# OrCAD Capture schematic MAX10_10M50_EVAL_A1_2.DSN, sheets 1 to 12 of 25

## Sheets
1 Title, Note, Block Diagram: title: MAX 10 FPGA 10M50 Evaluation Kit (6XX-44364R); rev: A1.2; company: Altera Technical Service, No.888 Bi Bo Road, Shanghai
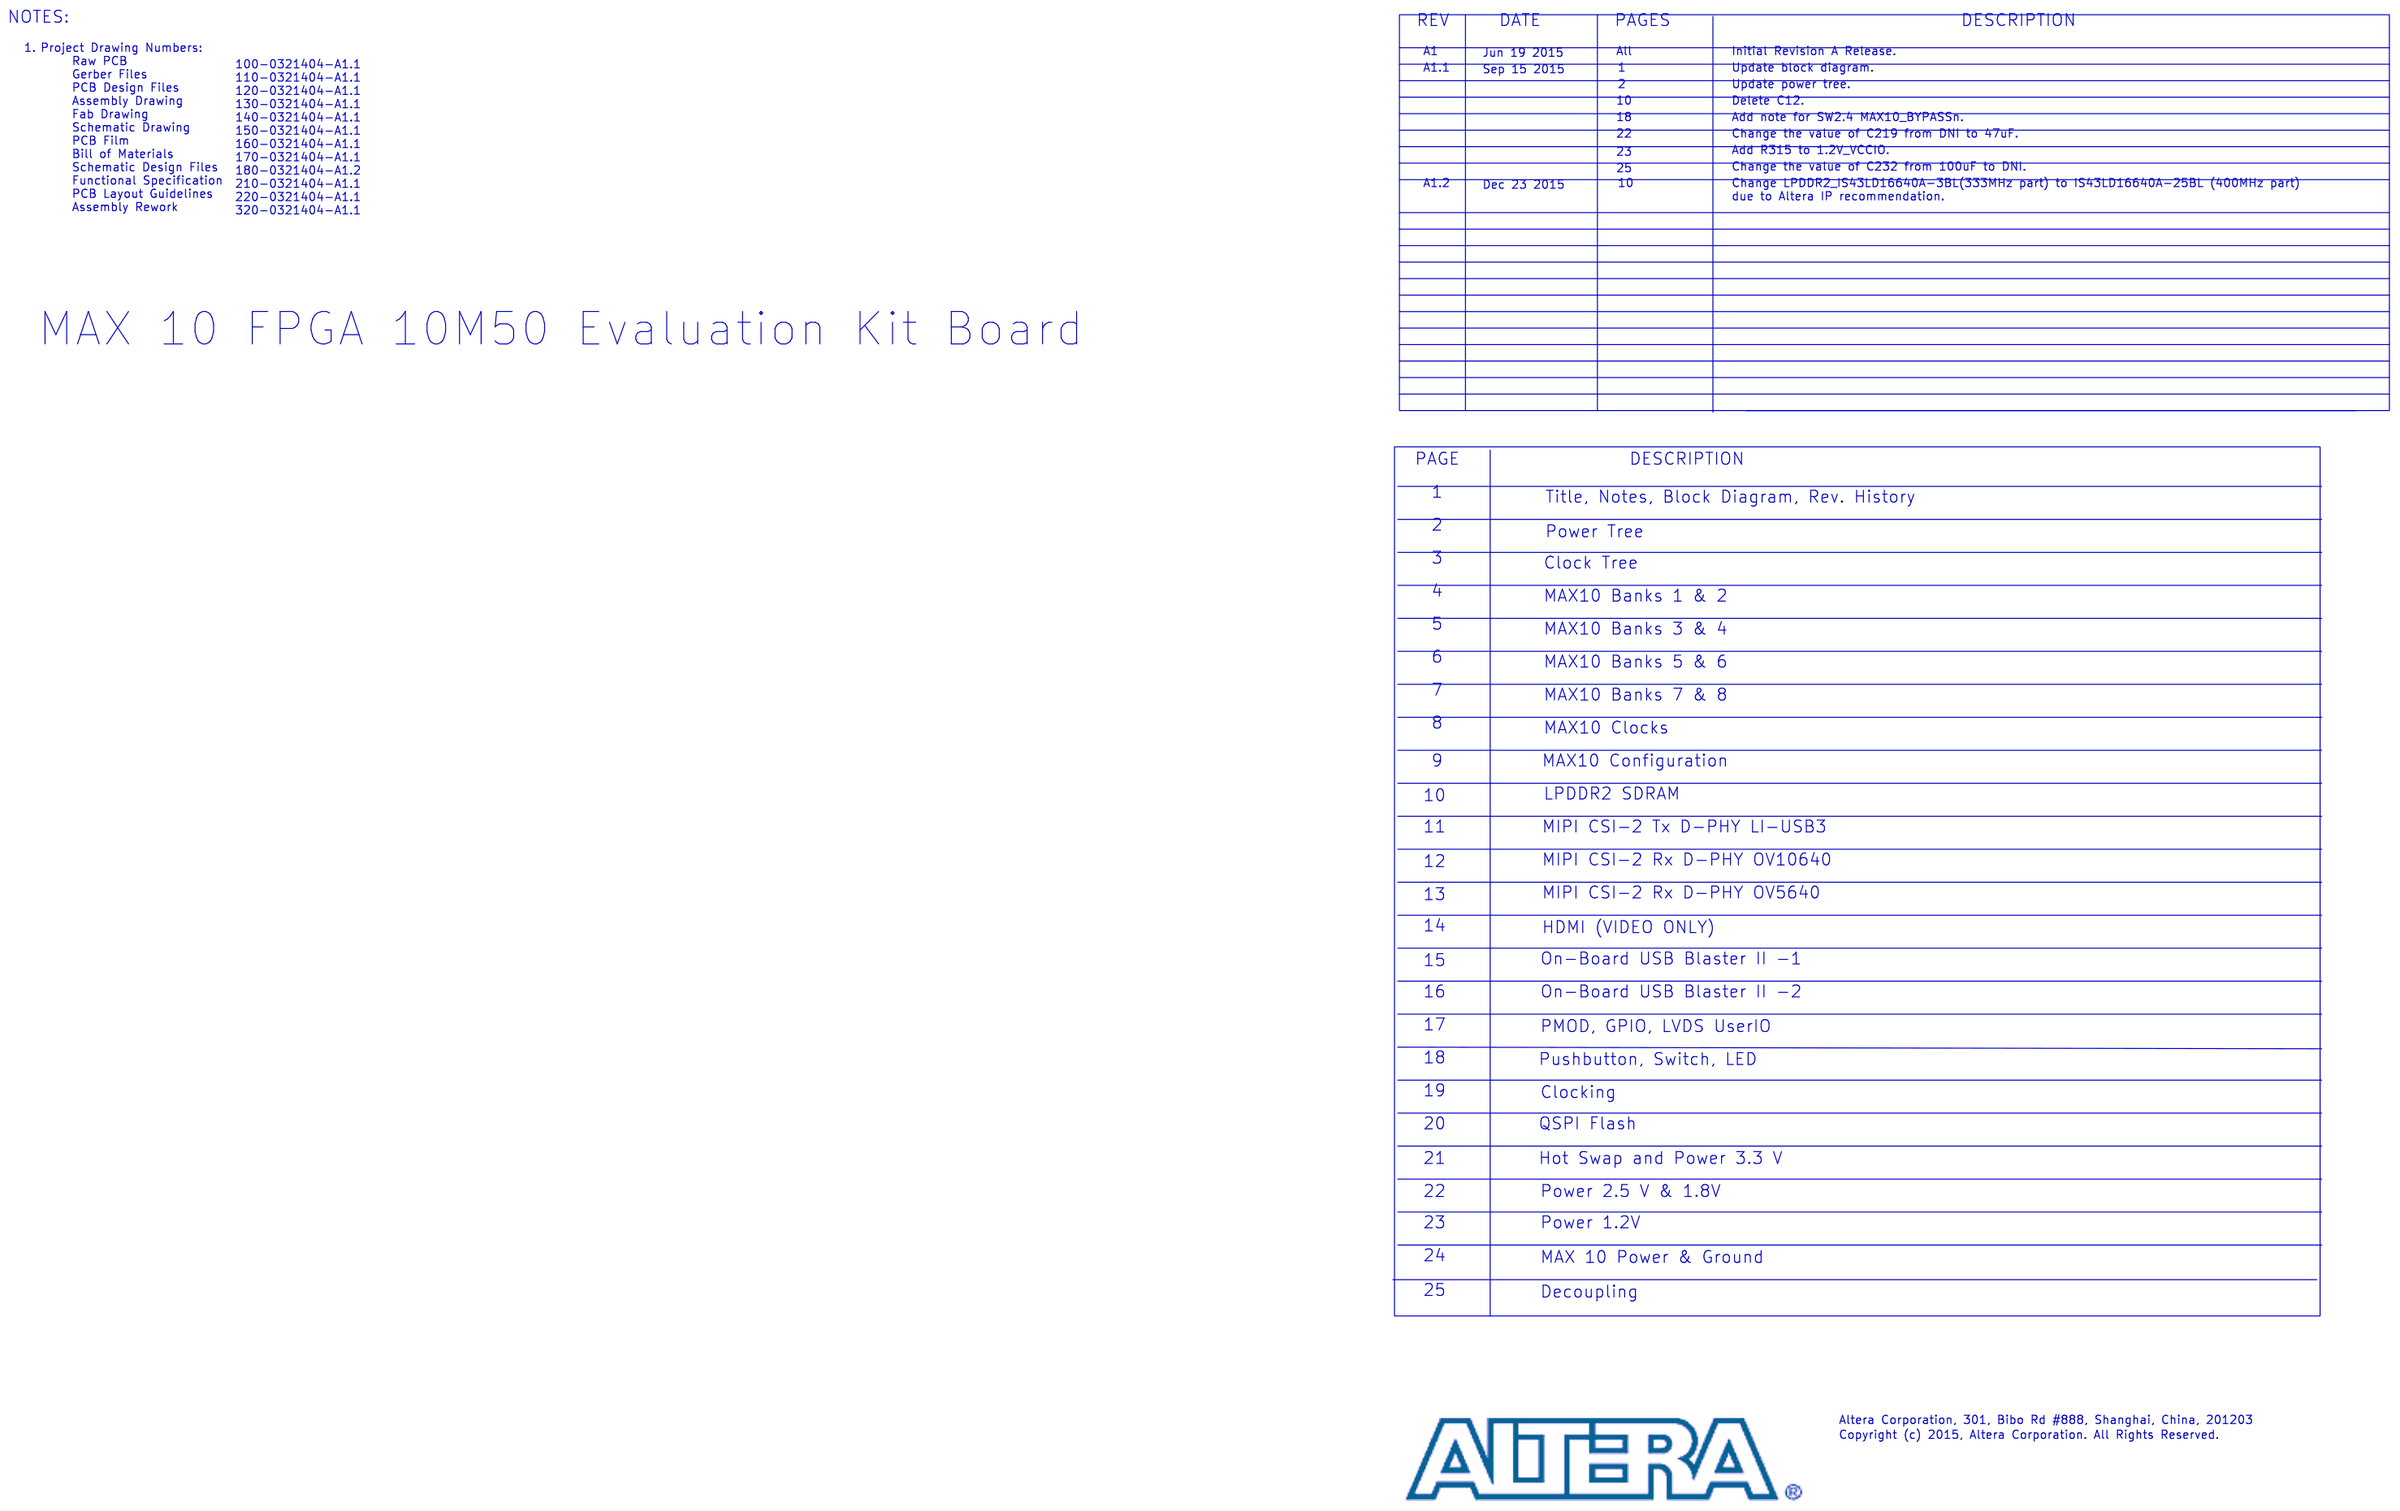
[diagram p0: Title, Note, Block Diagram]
2 Power Tree
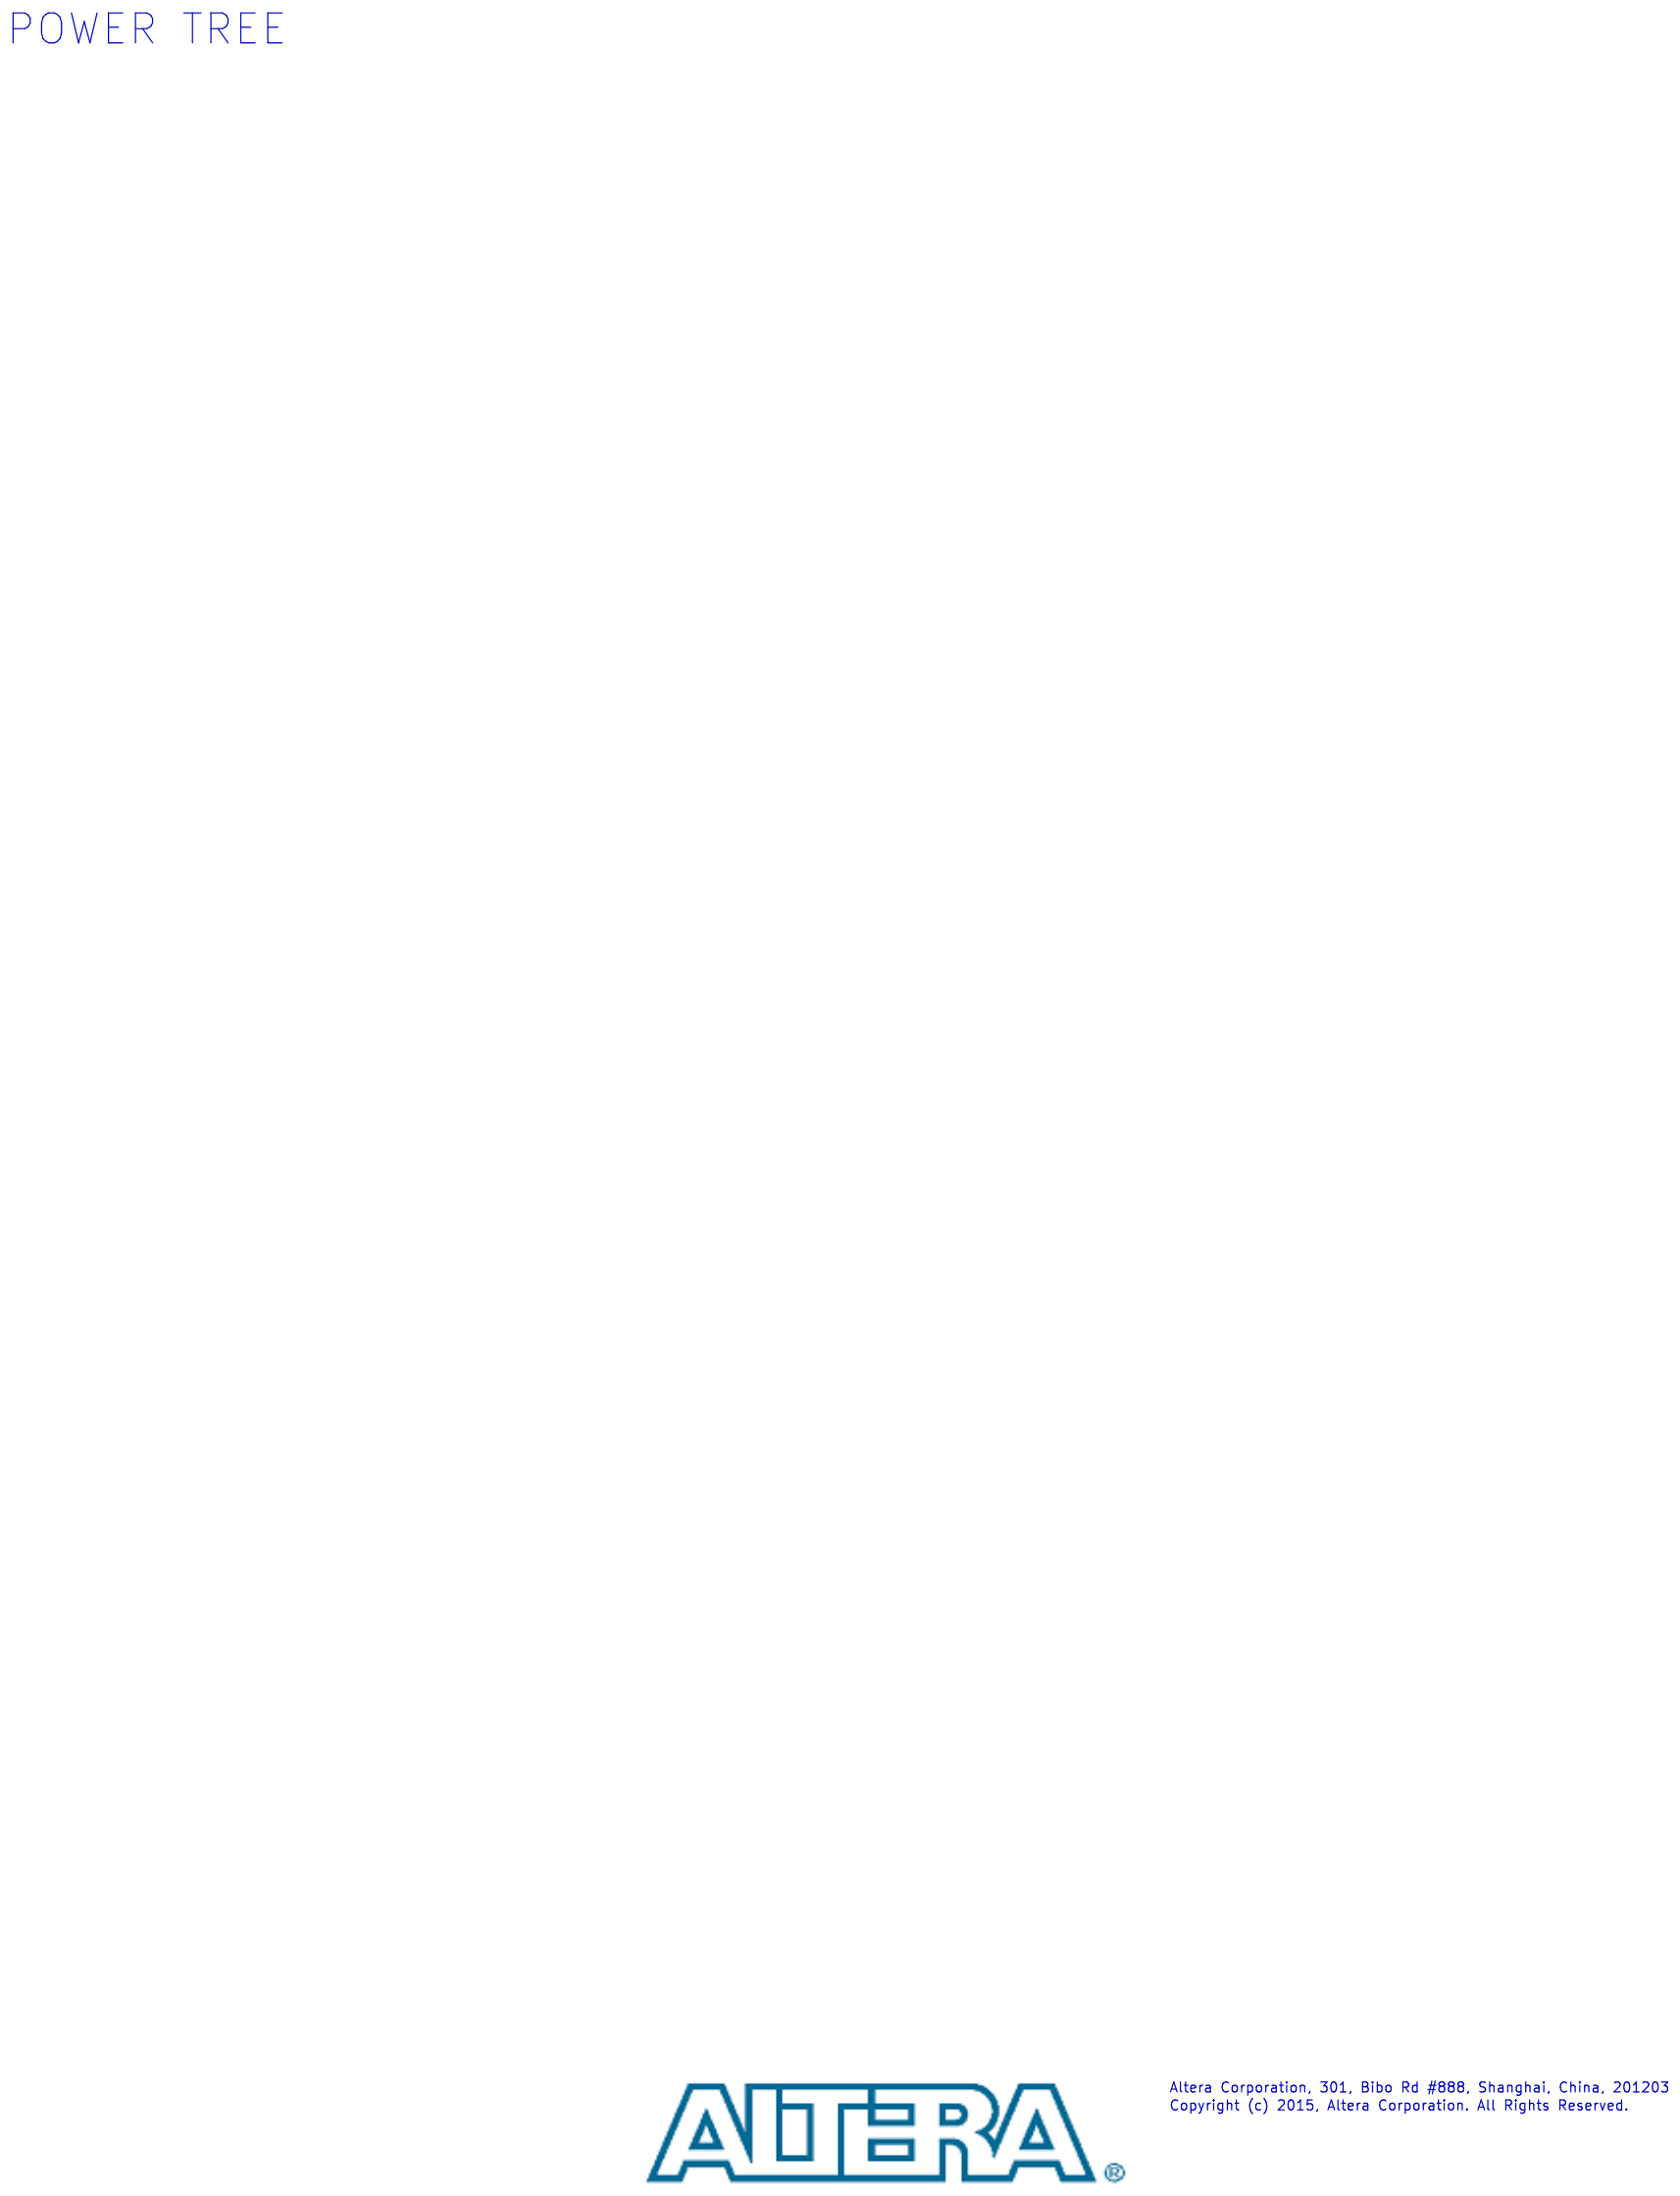
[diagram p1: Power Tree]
3 Clock Tree
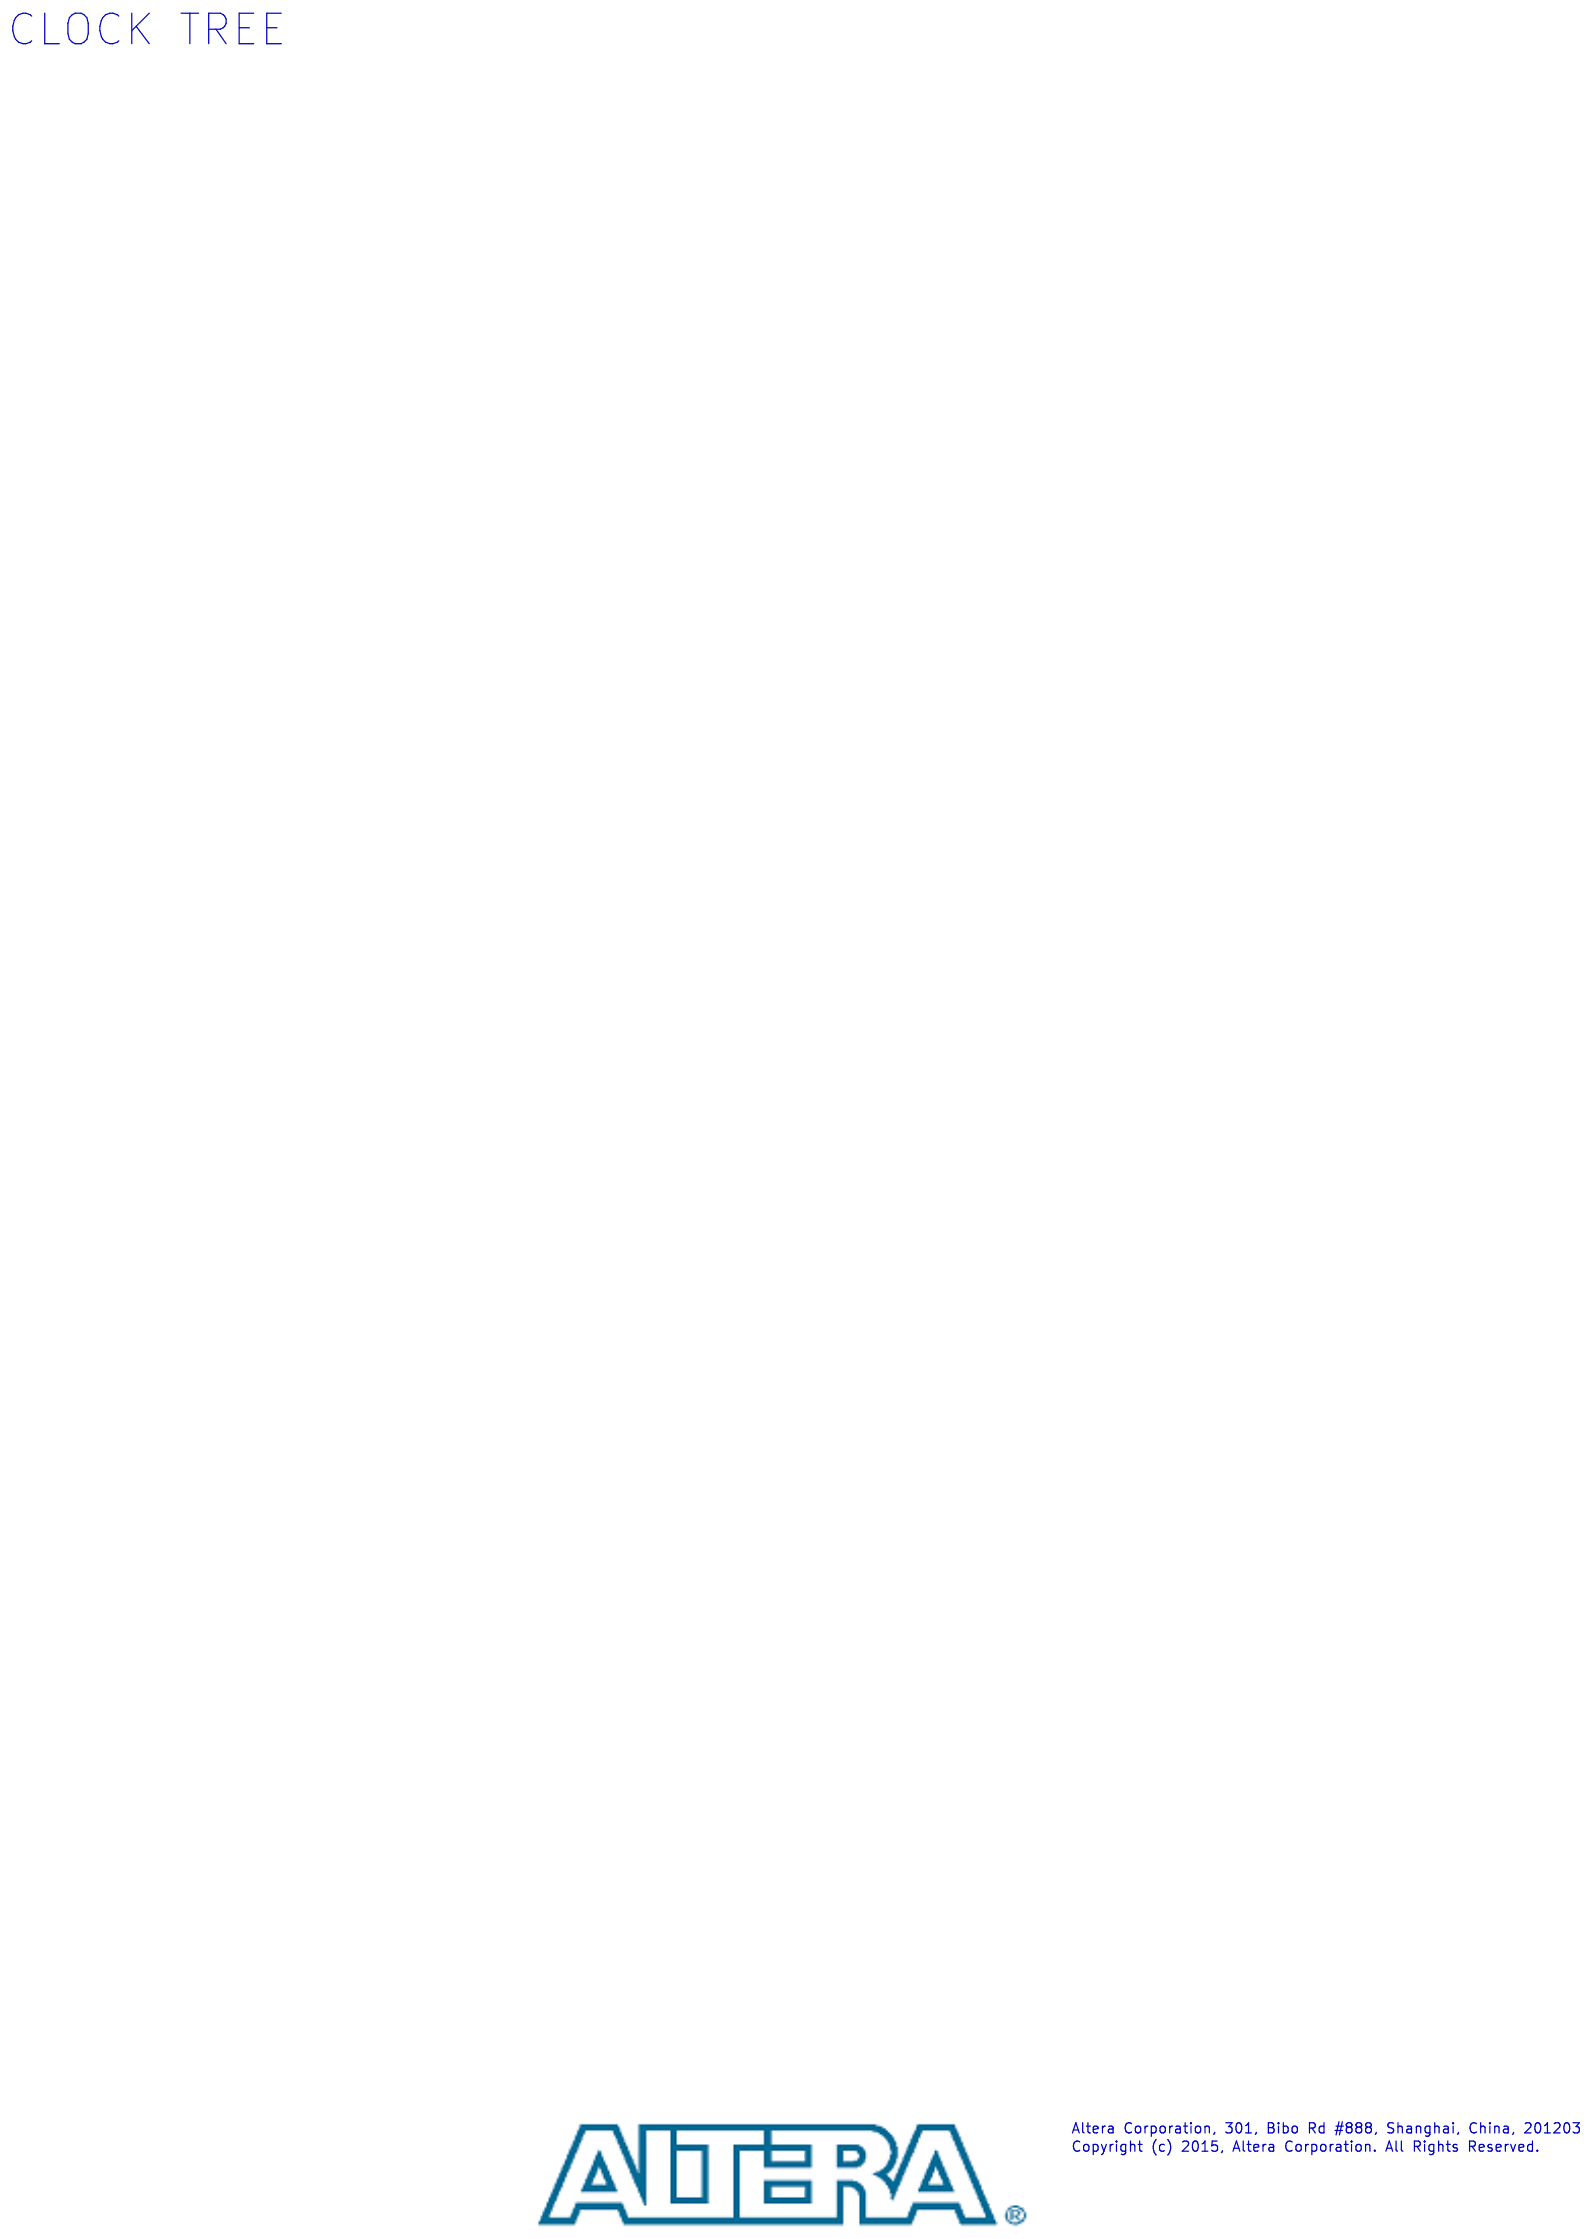
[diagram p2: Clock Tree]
4 MAX 10 Banks 1 & 2: size A3
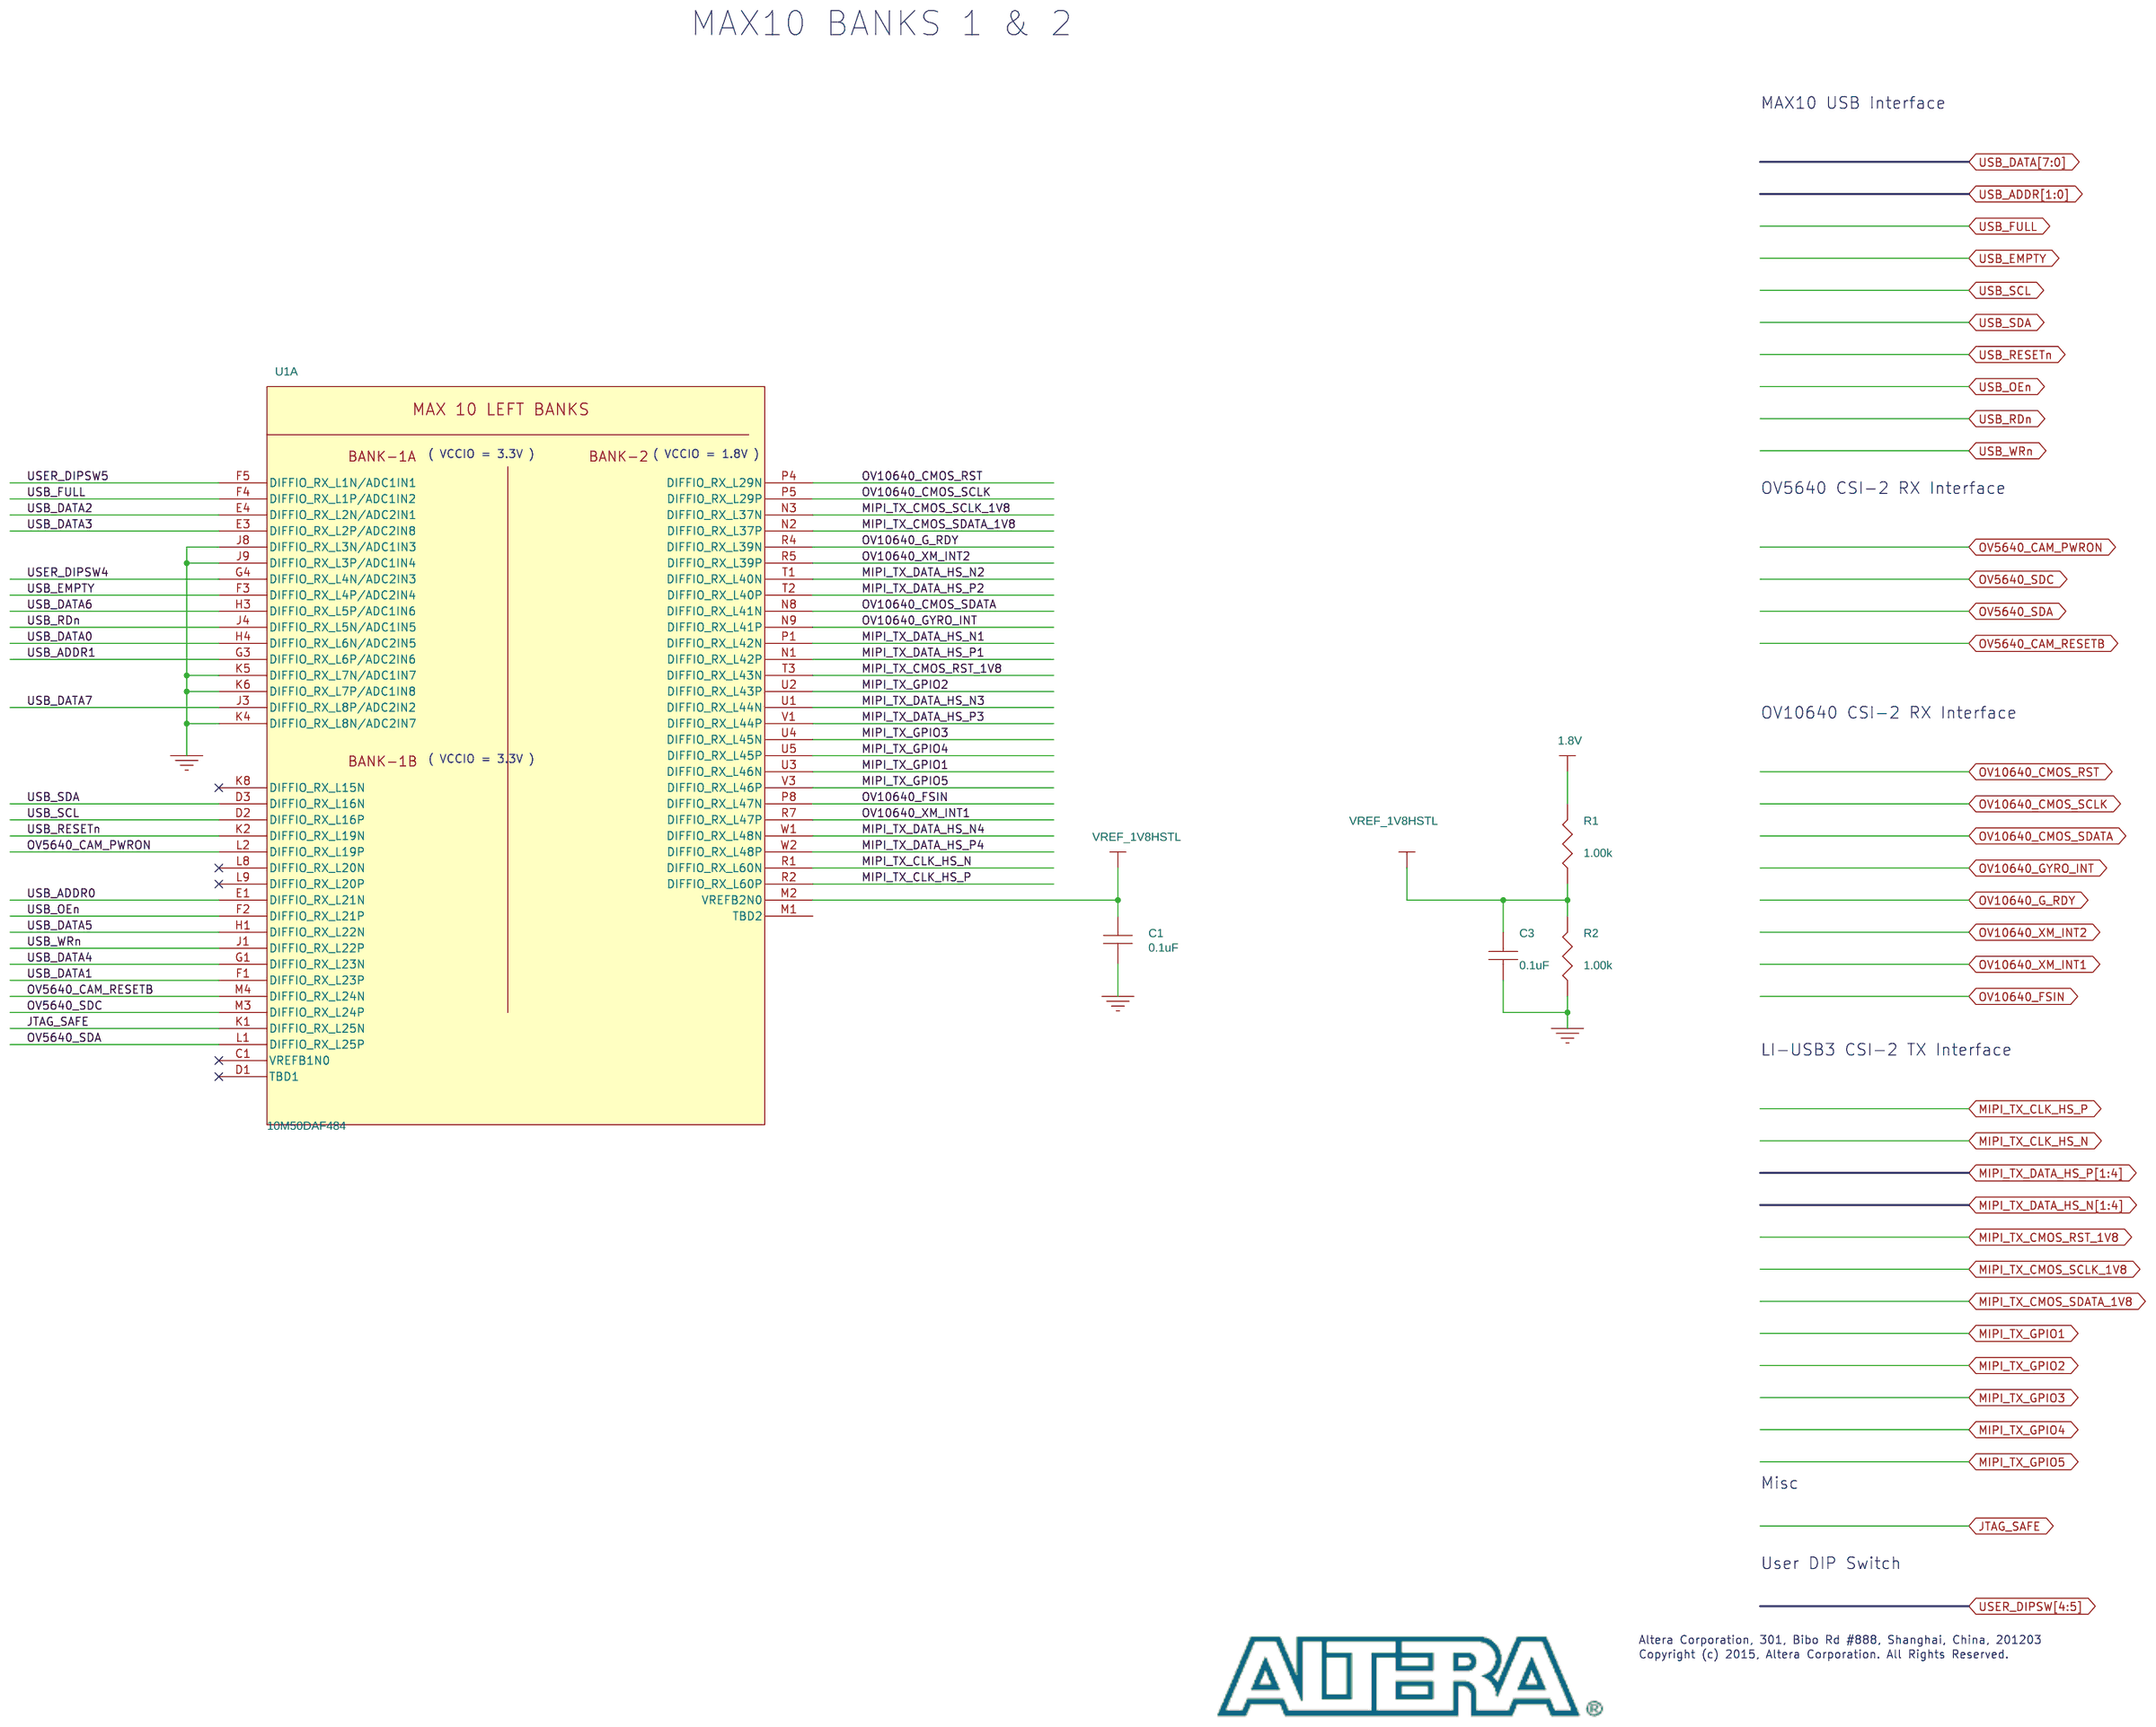
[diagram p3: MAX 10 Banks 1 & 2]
5 MAX 10 Banks 3 & 4: size A3
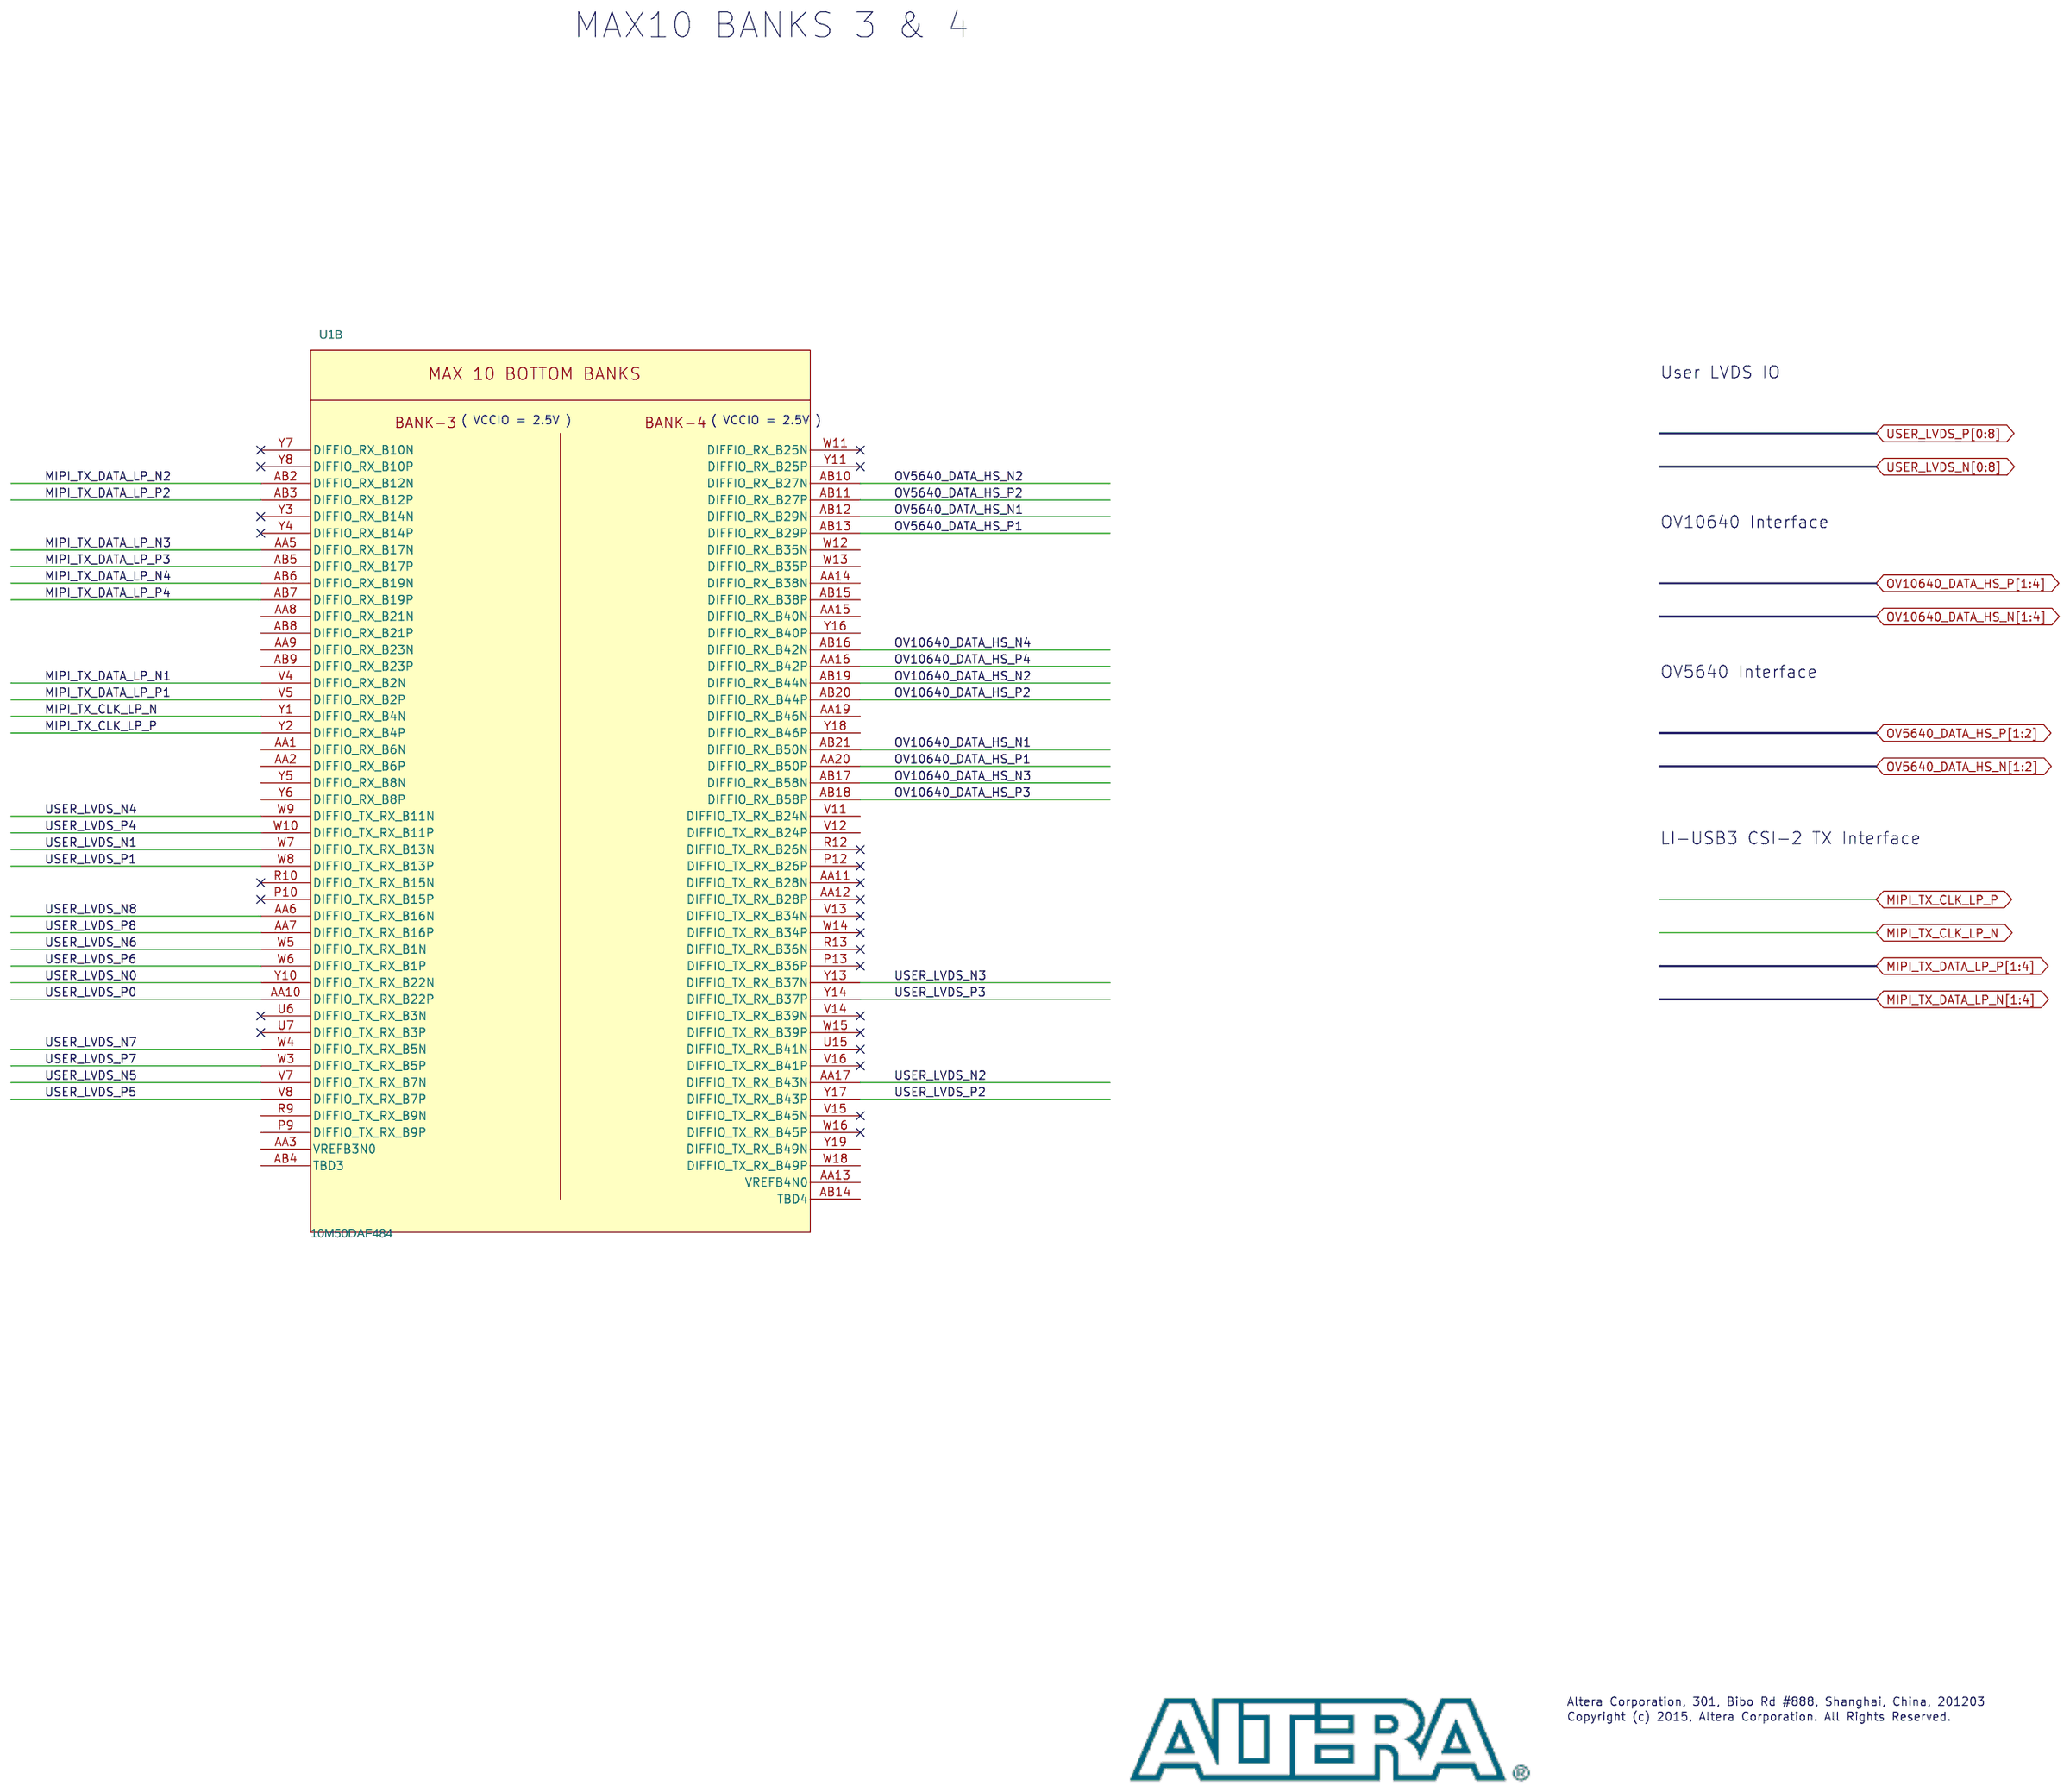
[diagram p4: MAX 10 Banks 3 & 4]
6 MAX 10 Banks 5 & 6: size A3
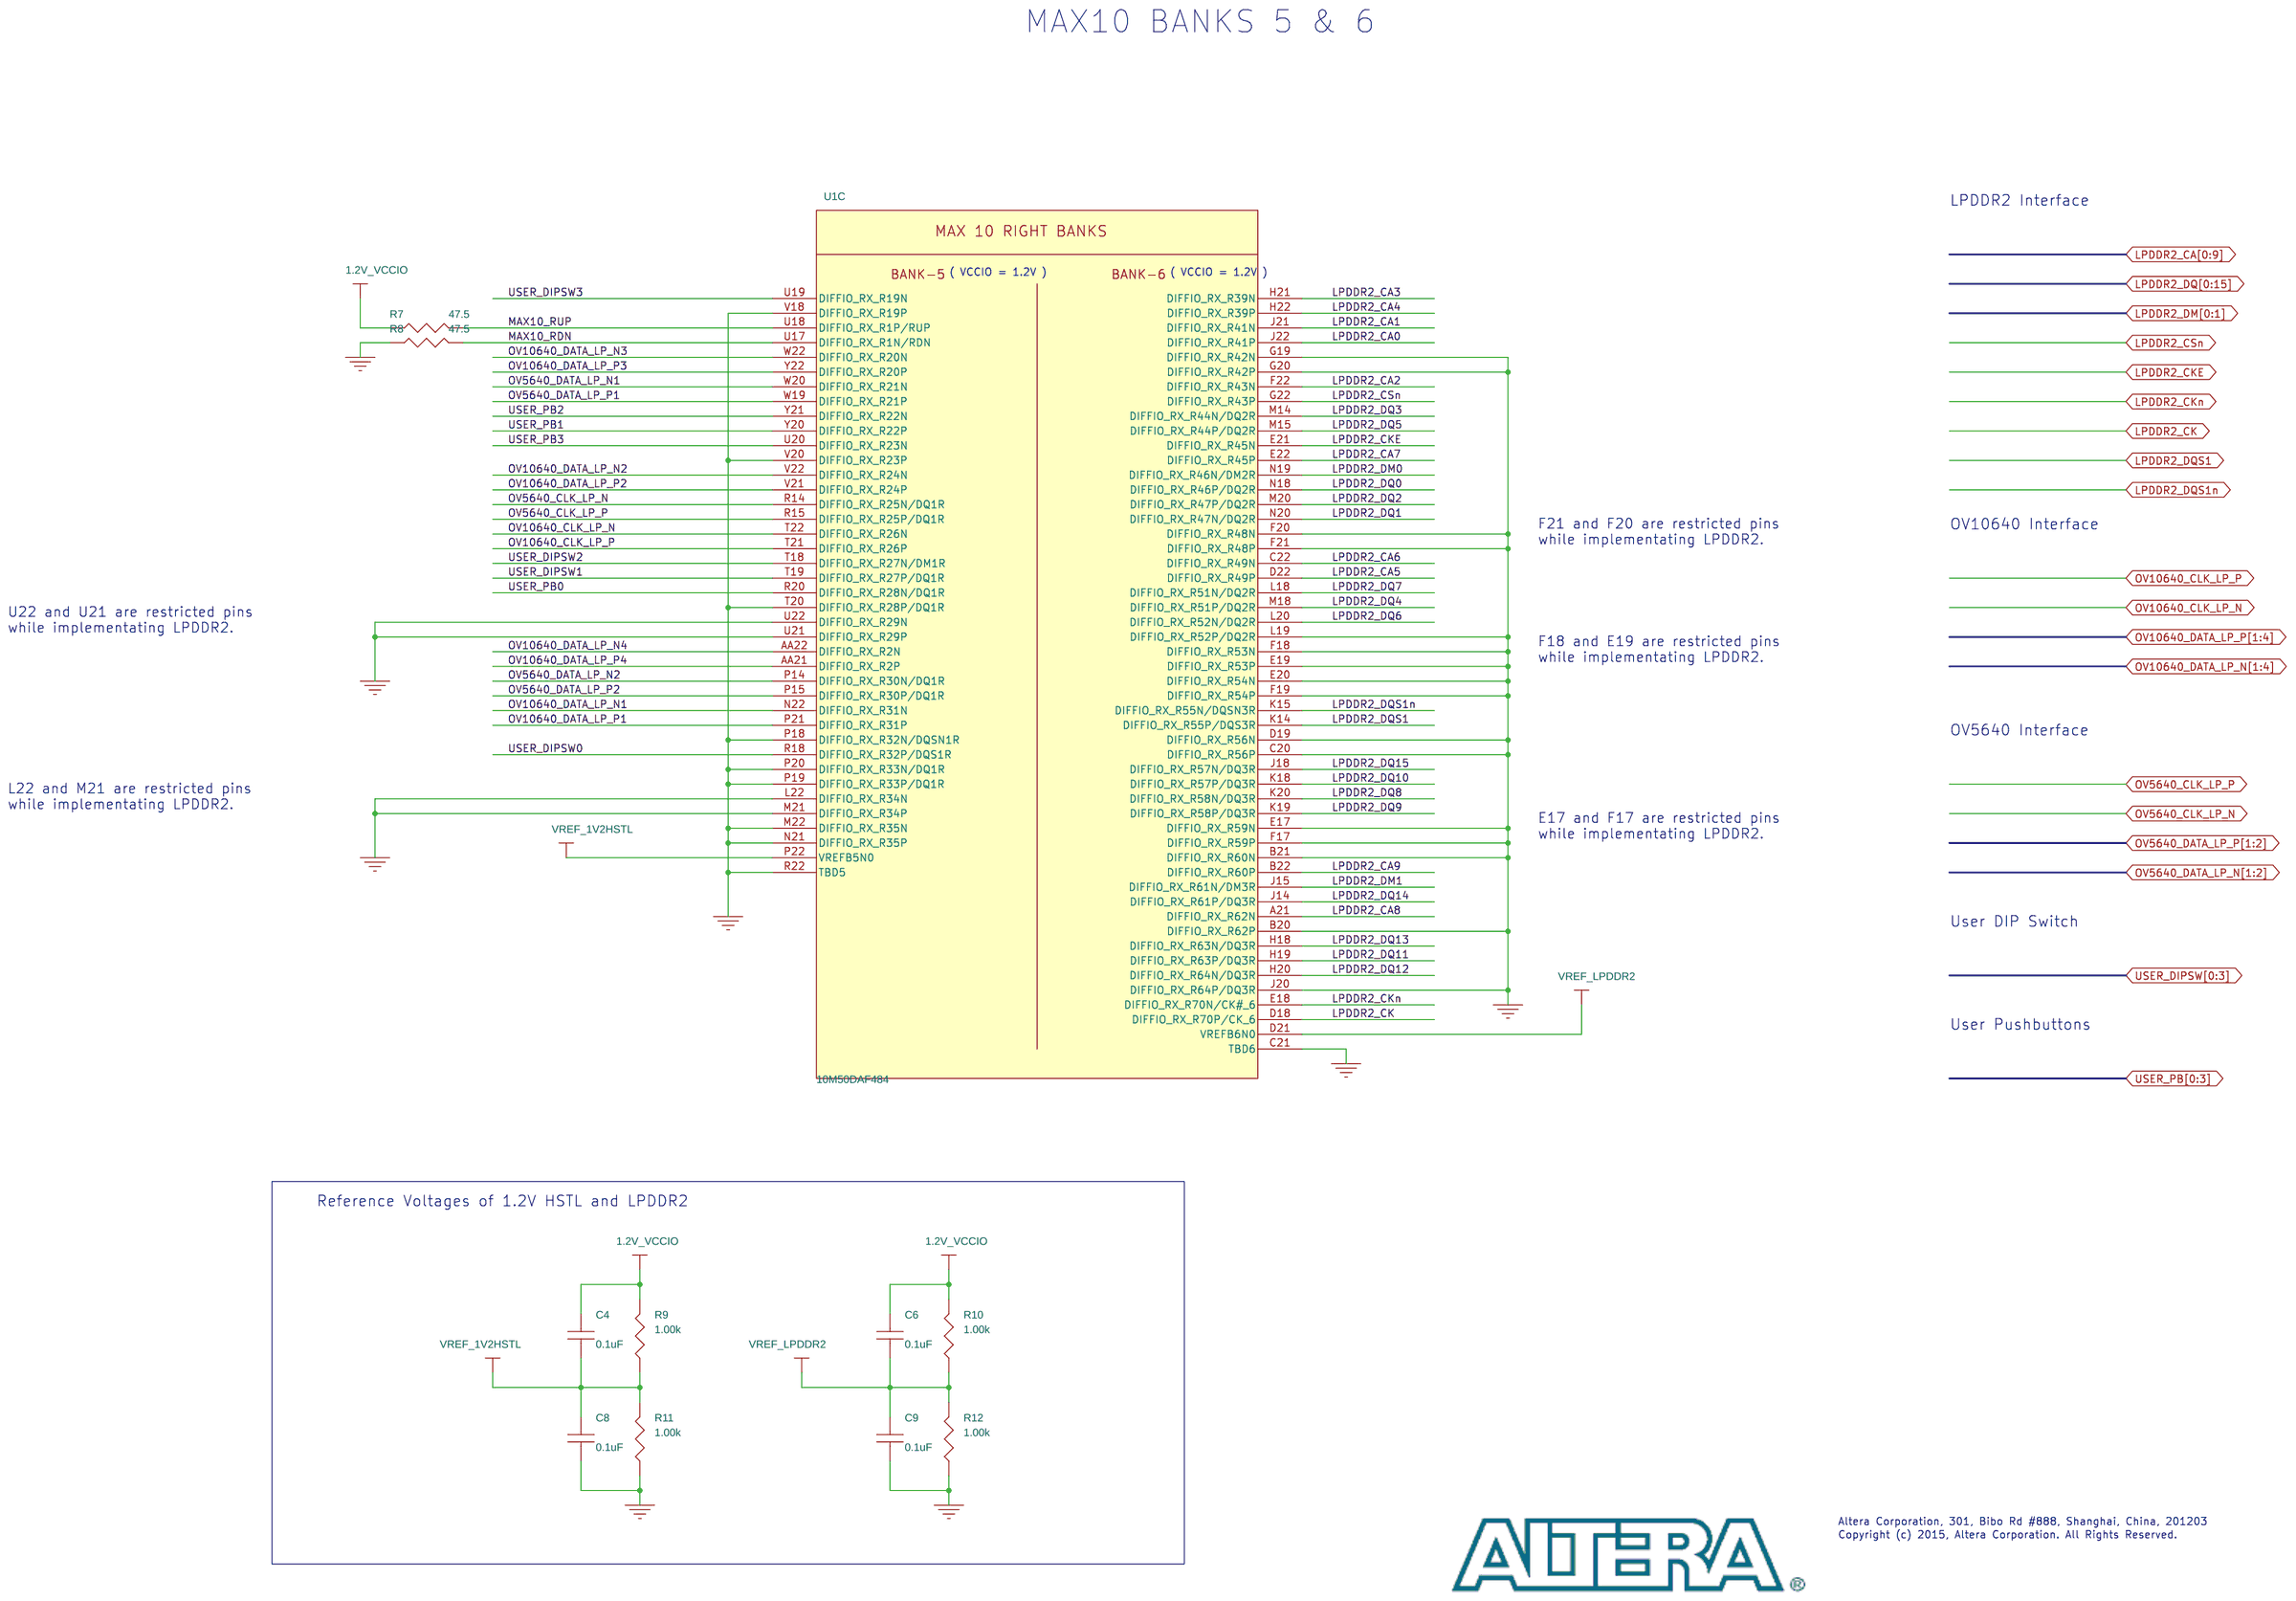
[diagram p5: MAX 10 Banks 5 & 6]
7 MAX 10 Banks 7 & 8: size A3
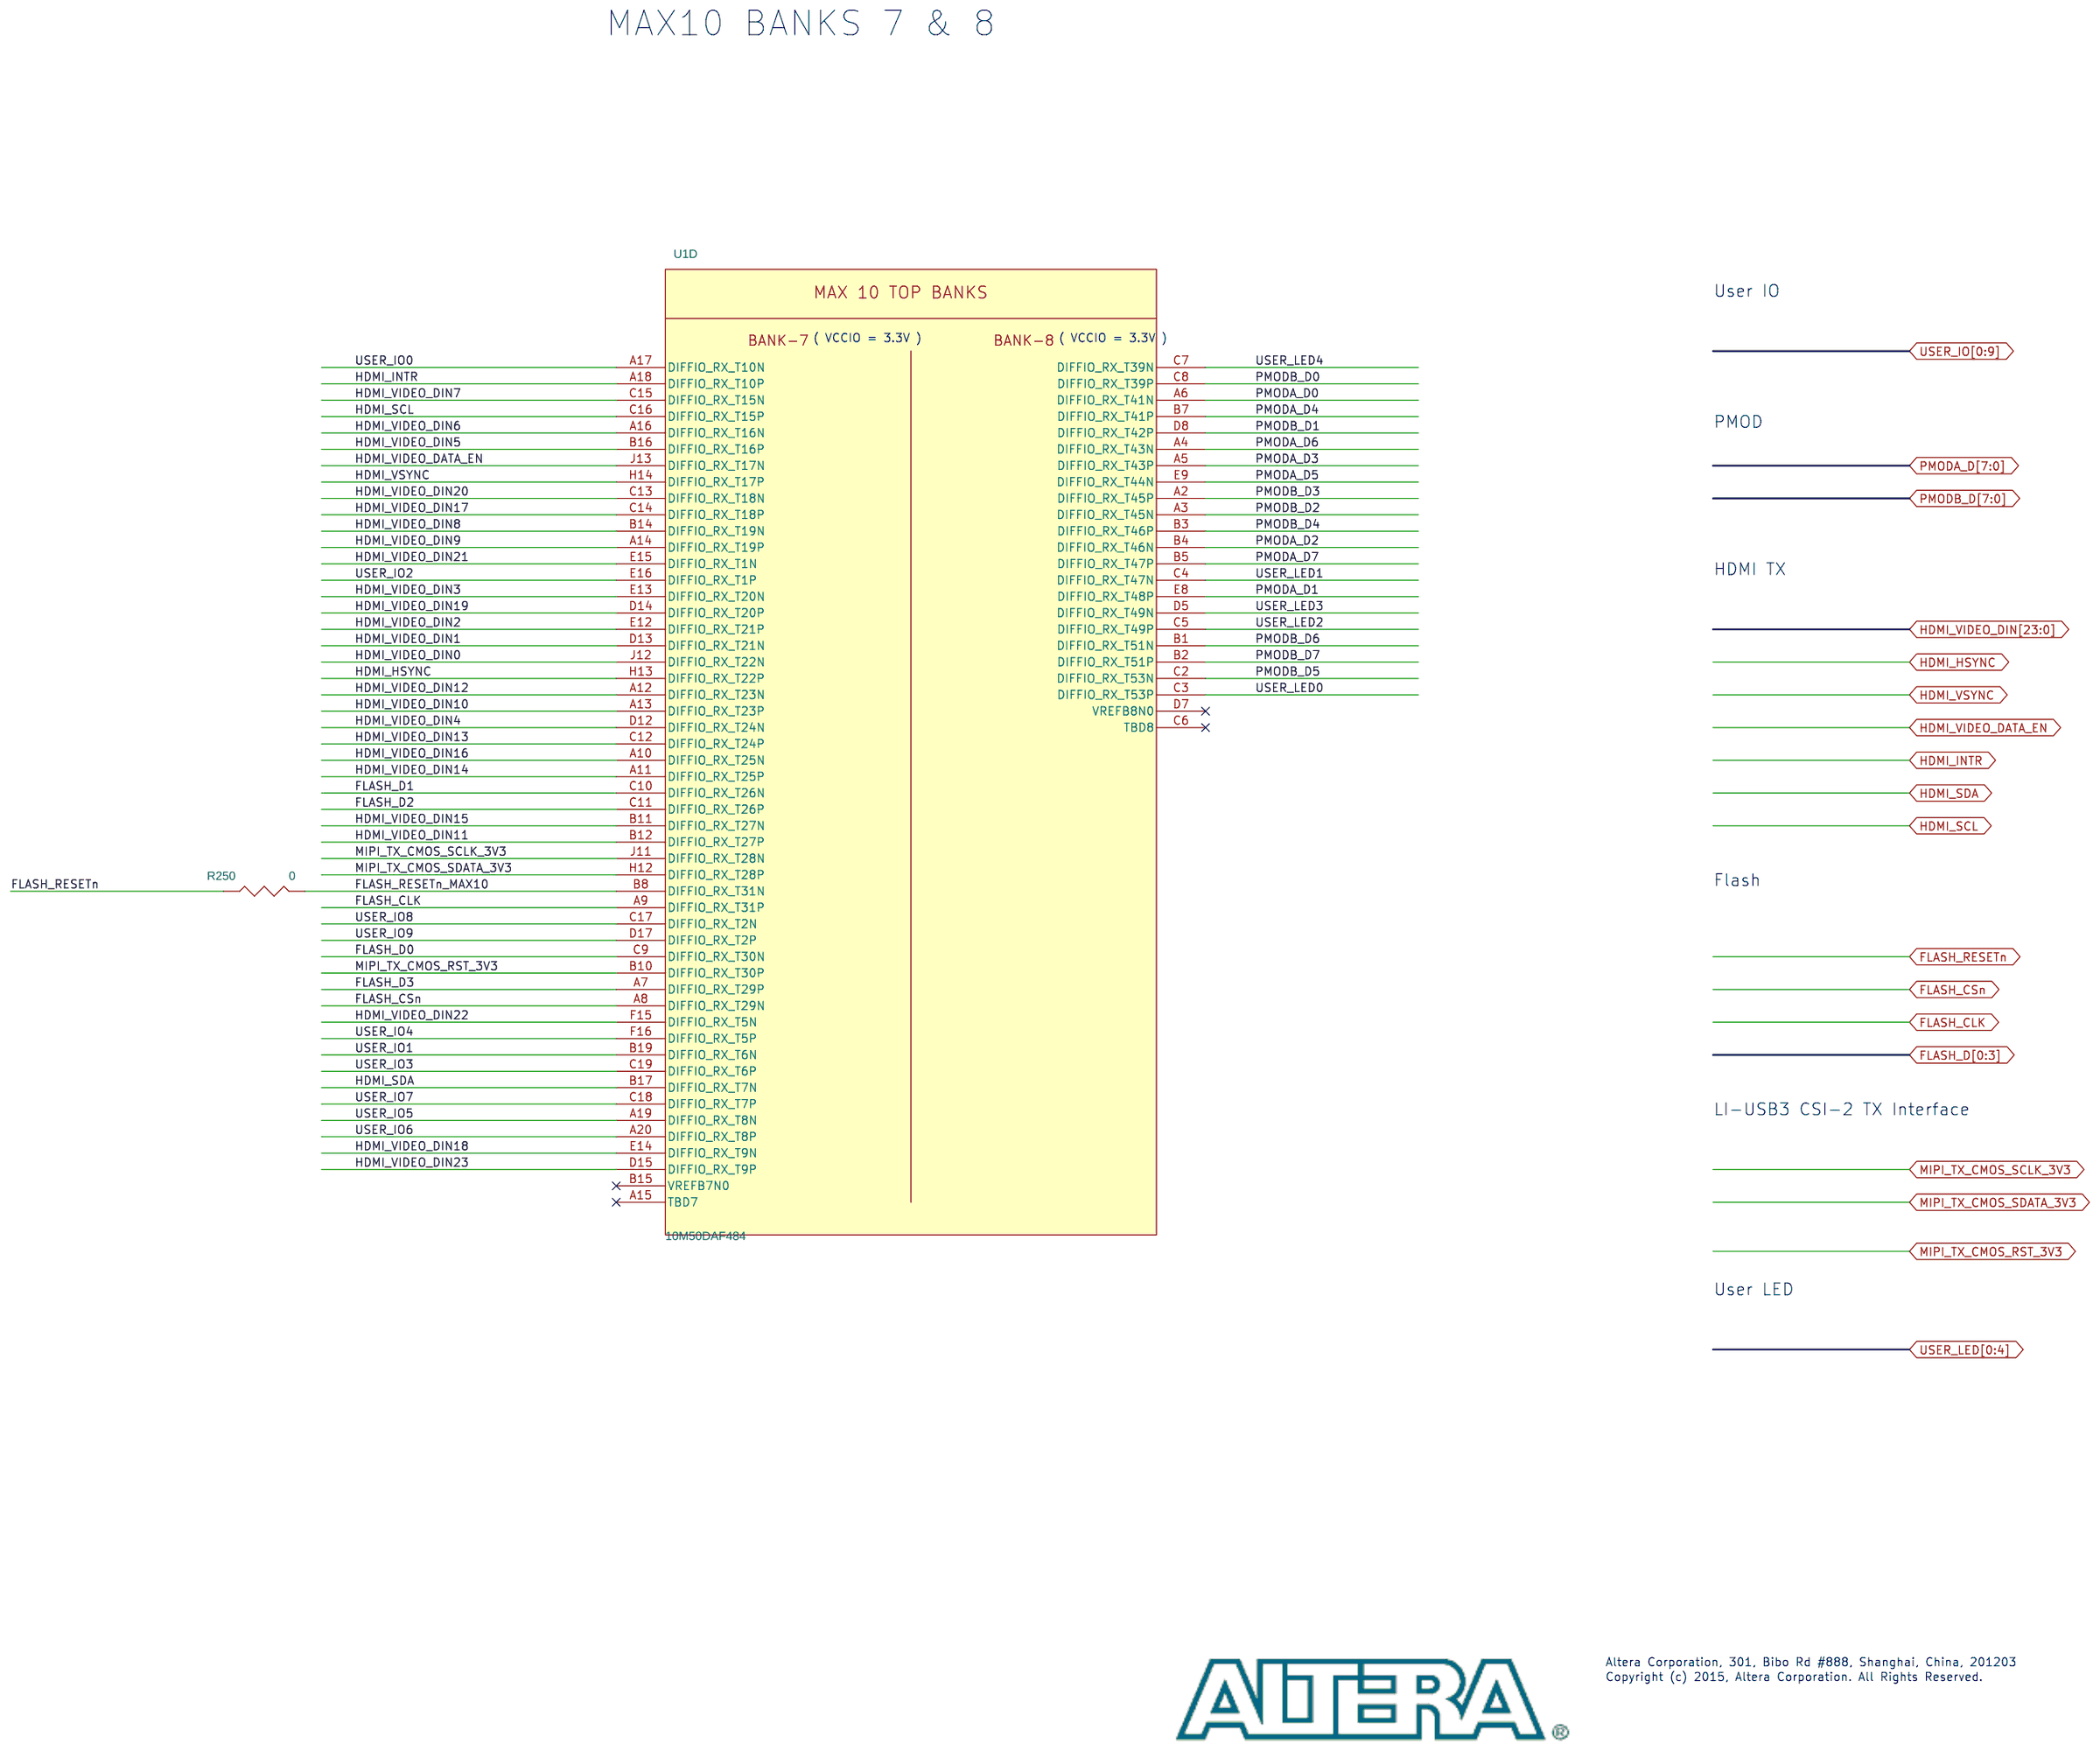
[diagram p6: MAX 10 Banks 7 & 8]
8 MAX 10 Clocks: size A3
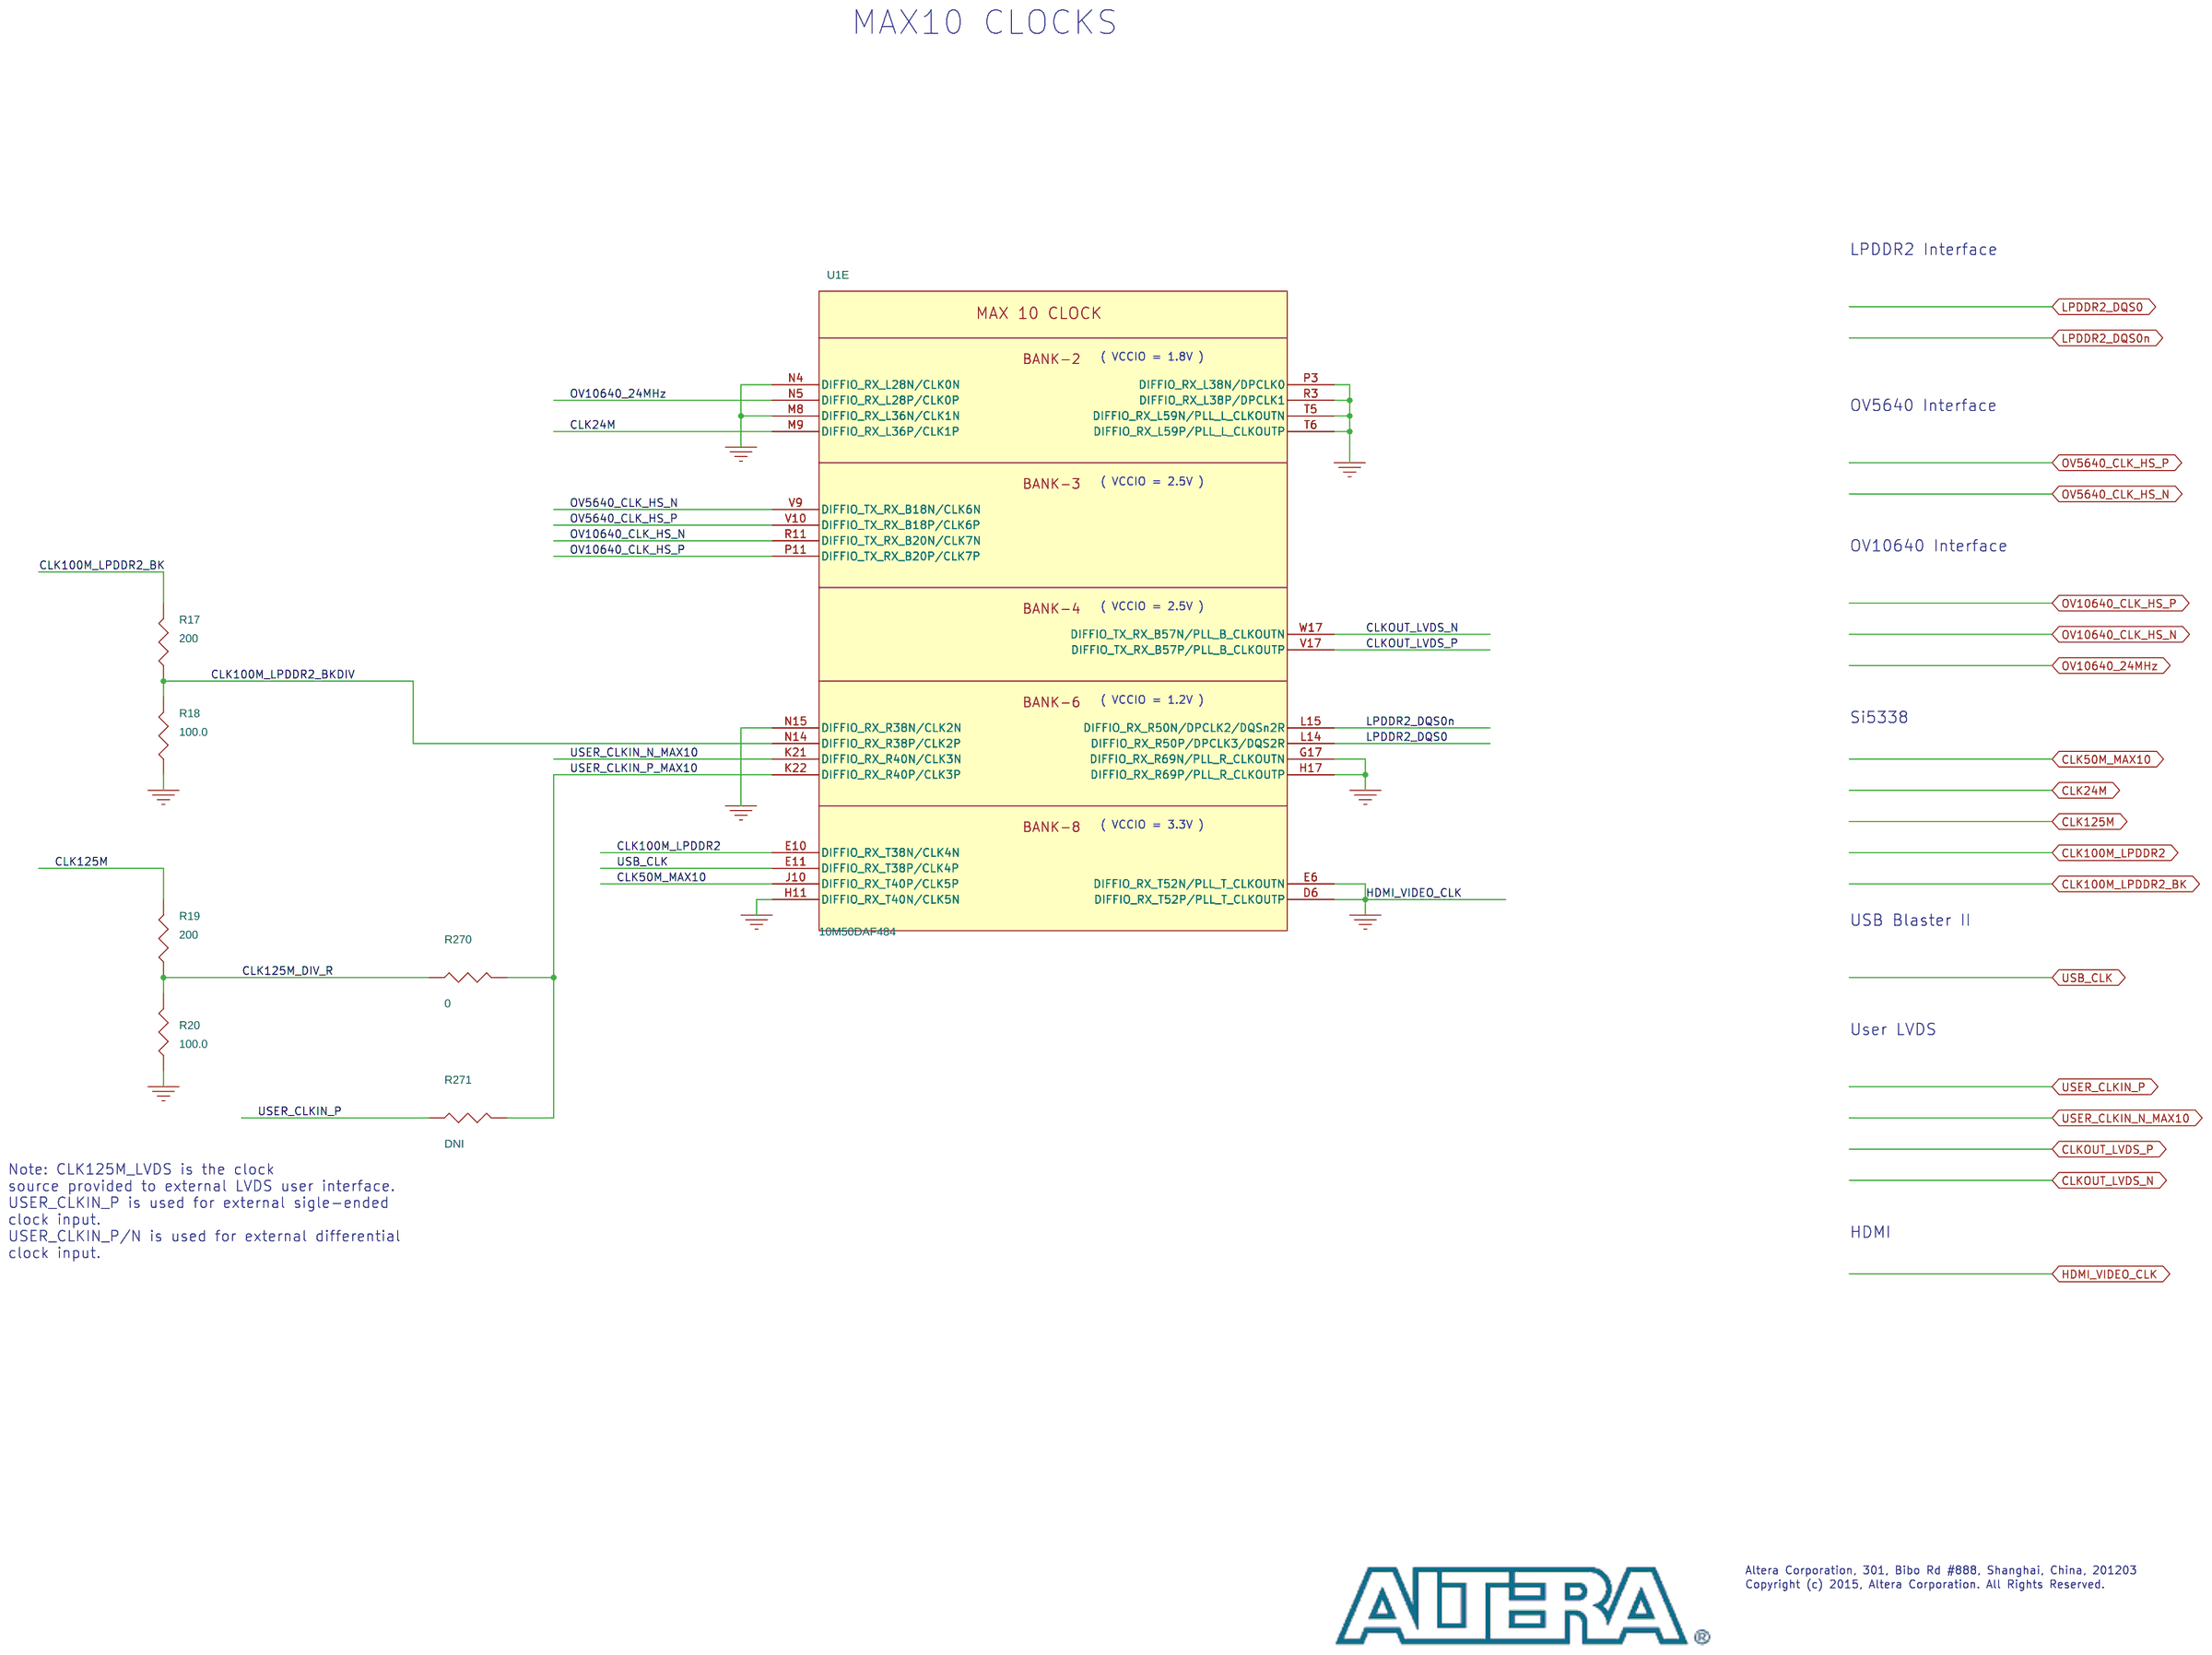
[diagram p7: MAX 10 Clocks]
9 MAX 10 Configuration: size A3
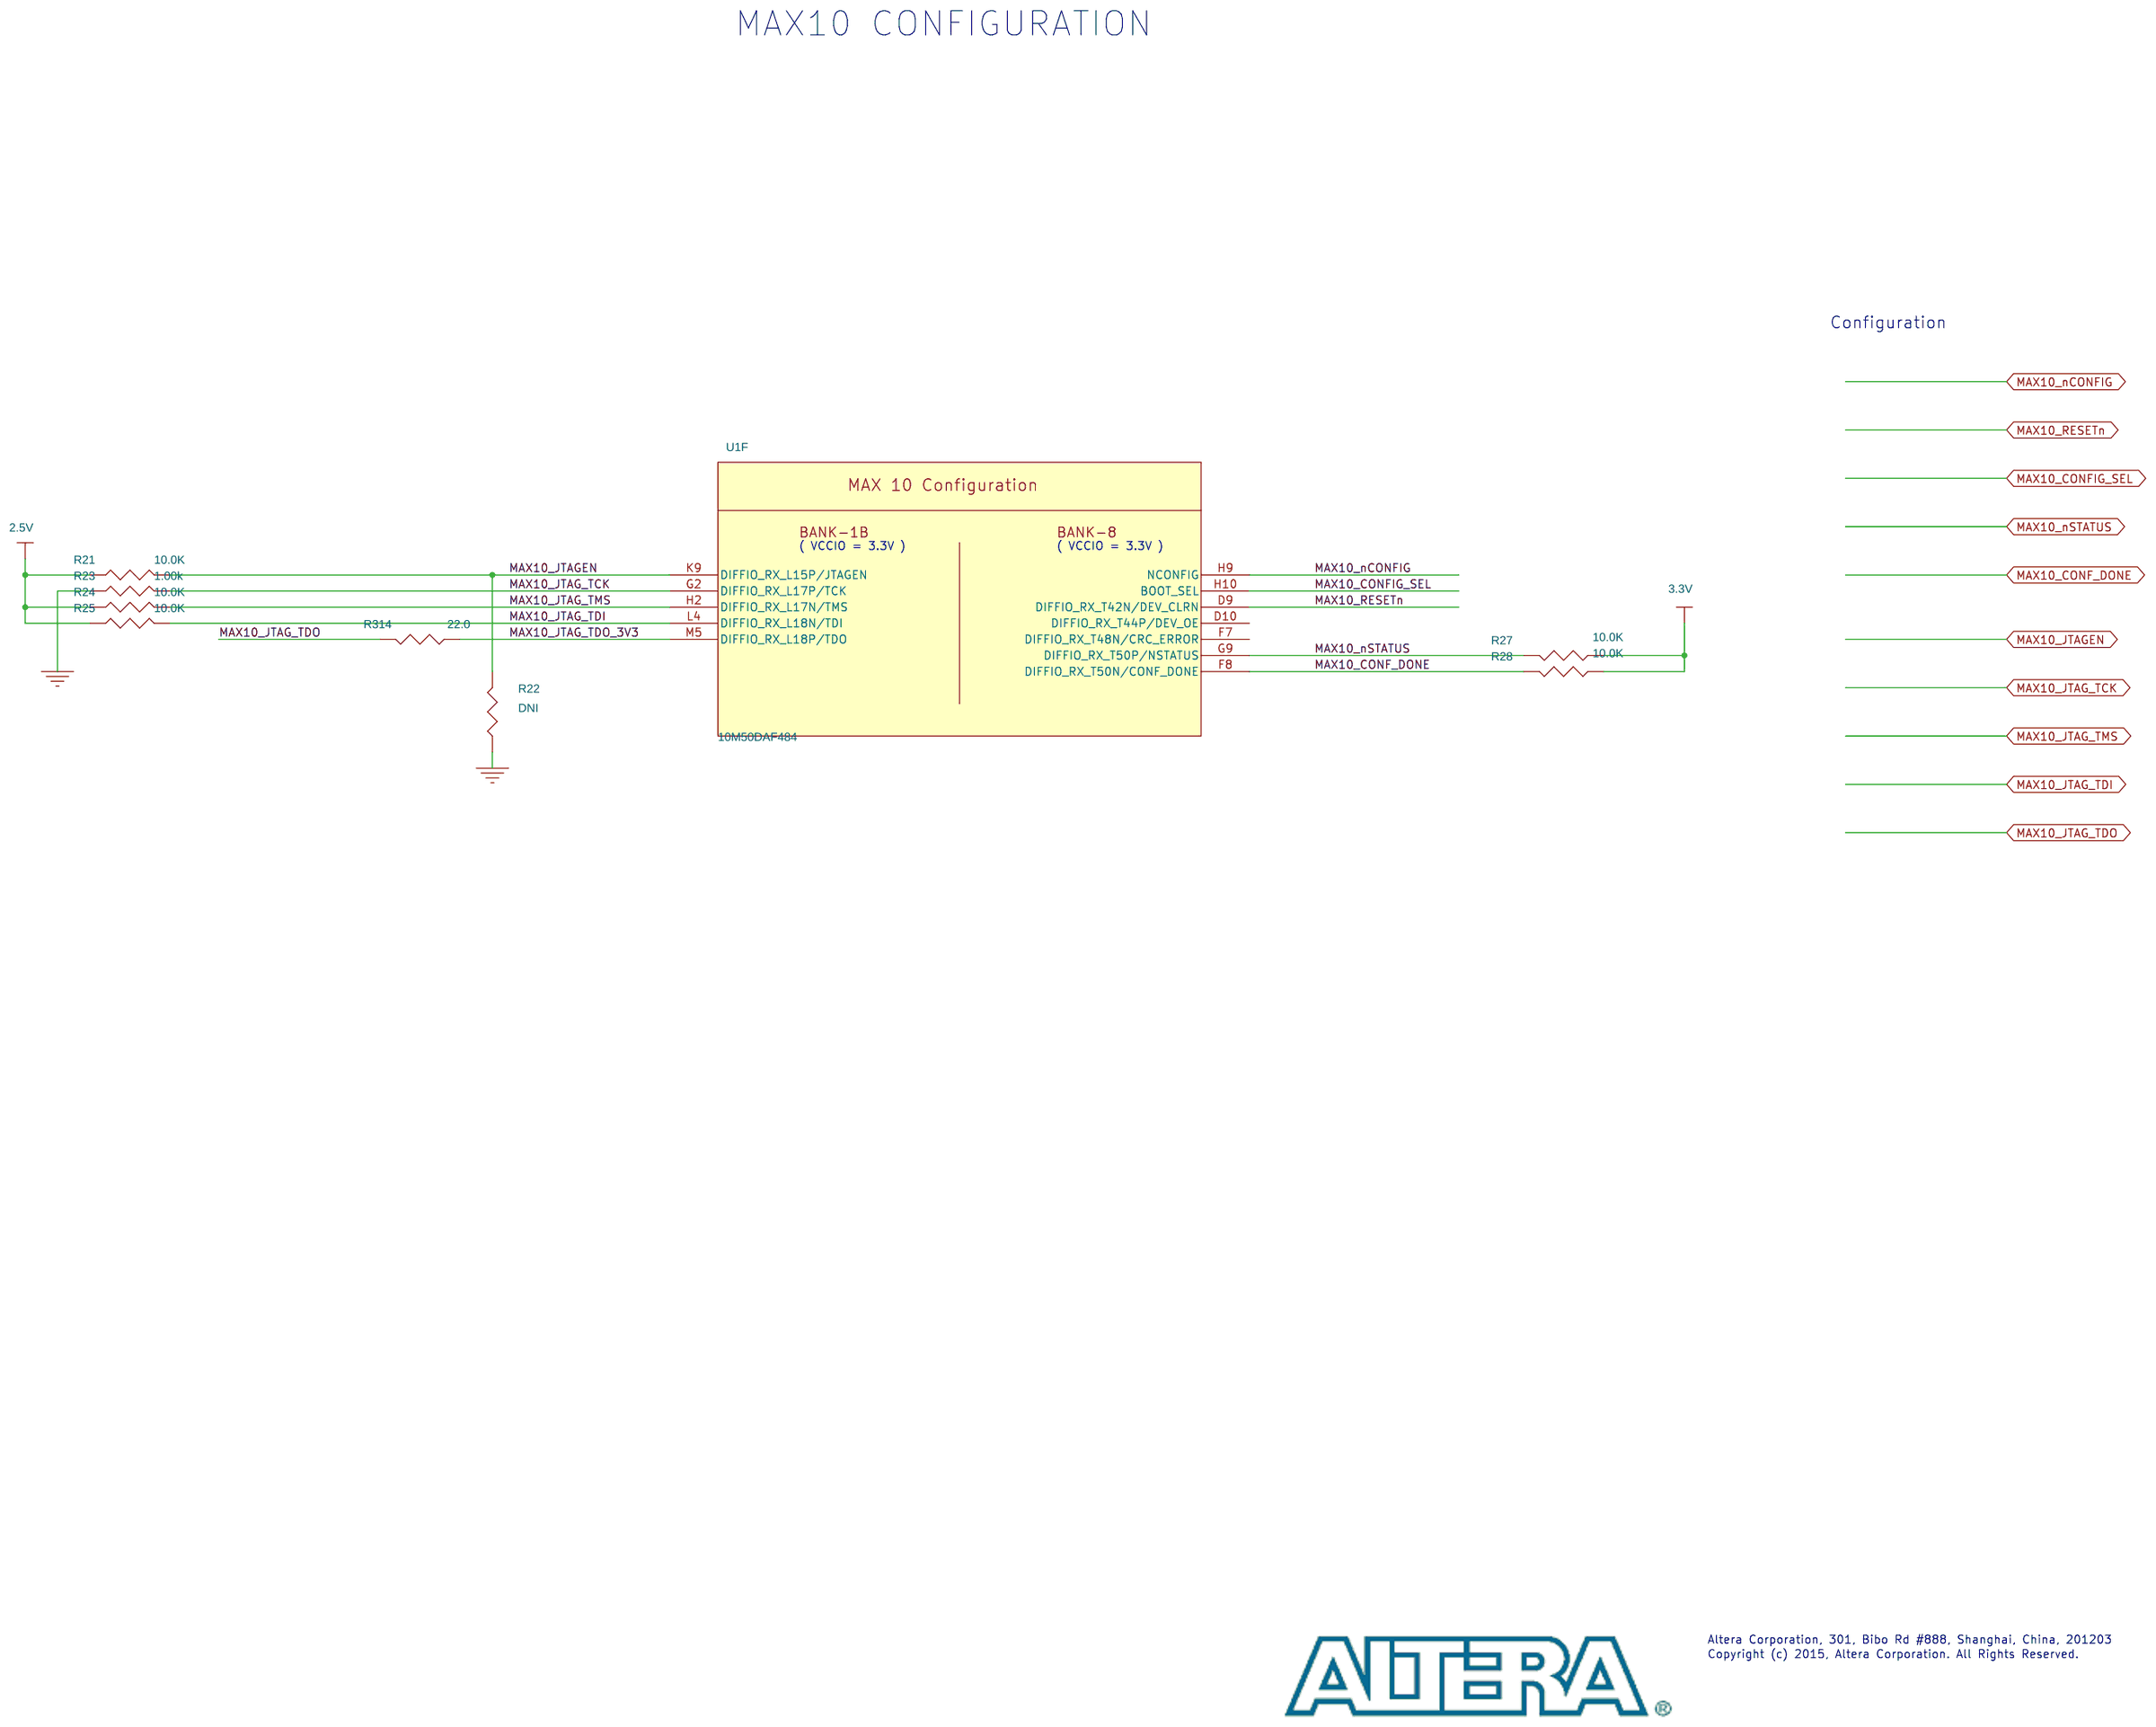
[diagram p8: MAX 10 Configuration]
10 LPDDR2 SDRAM: size A3
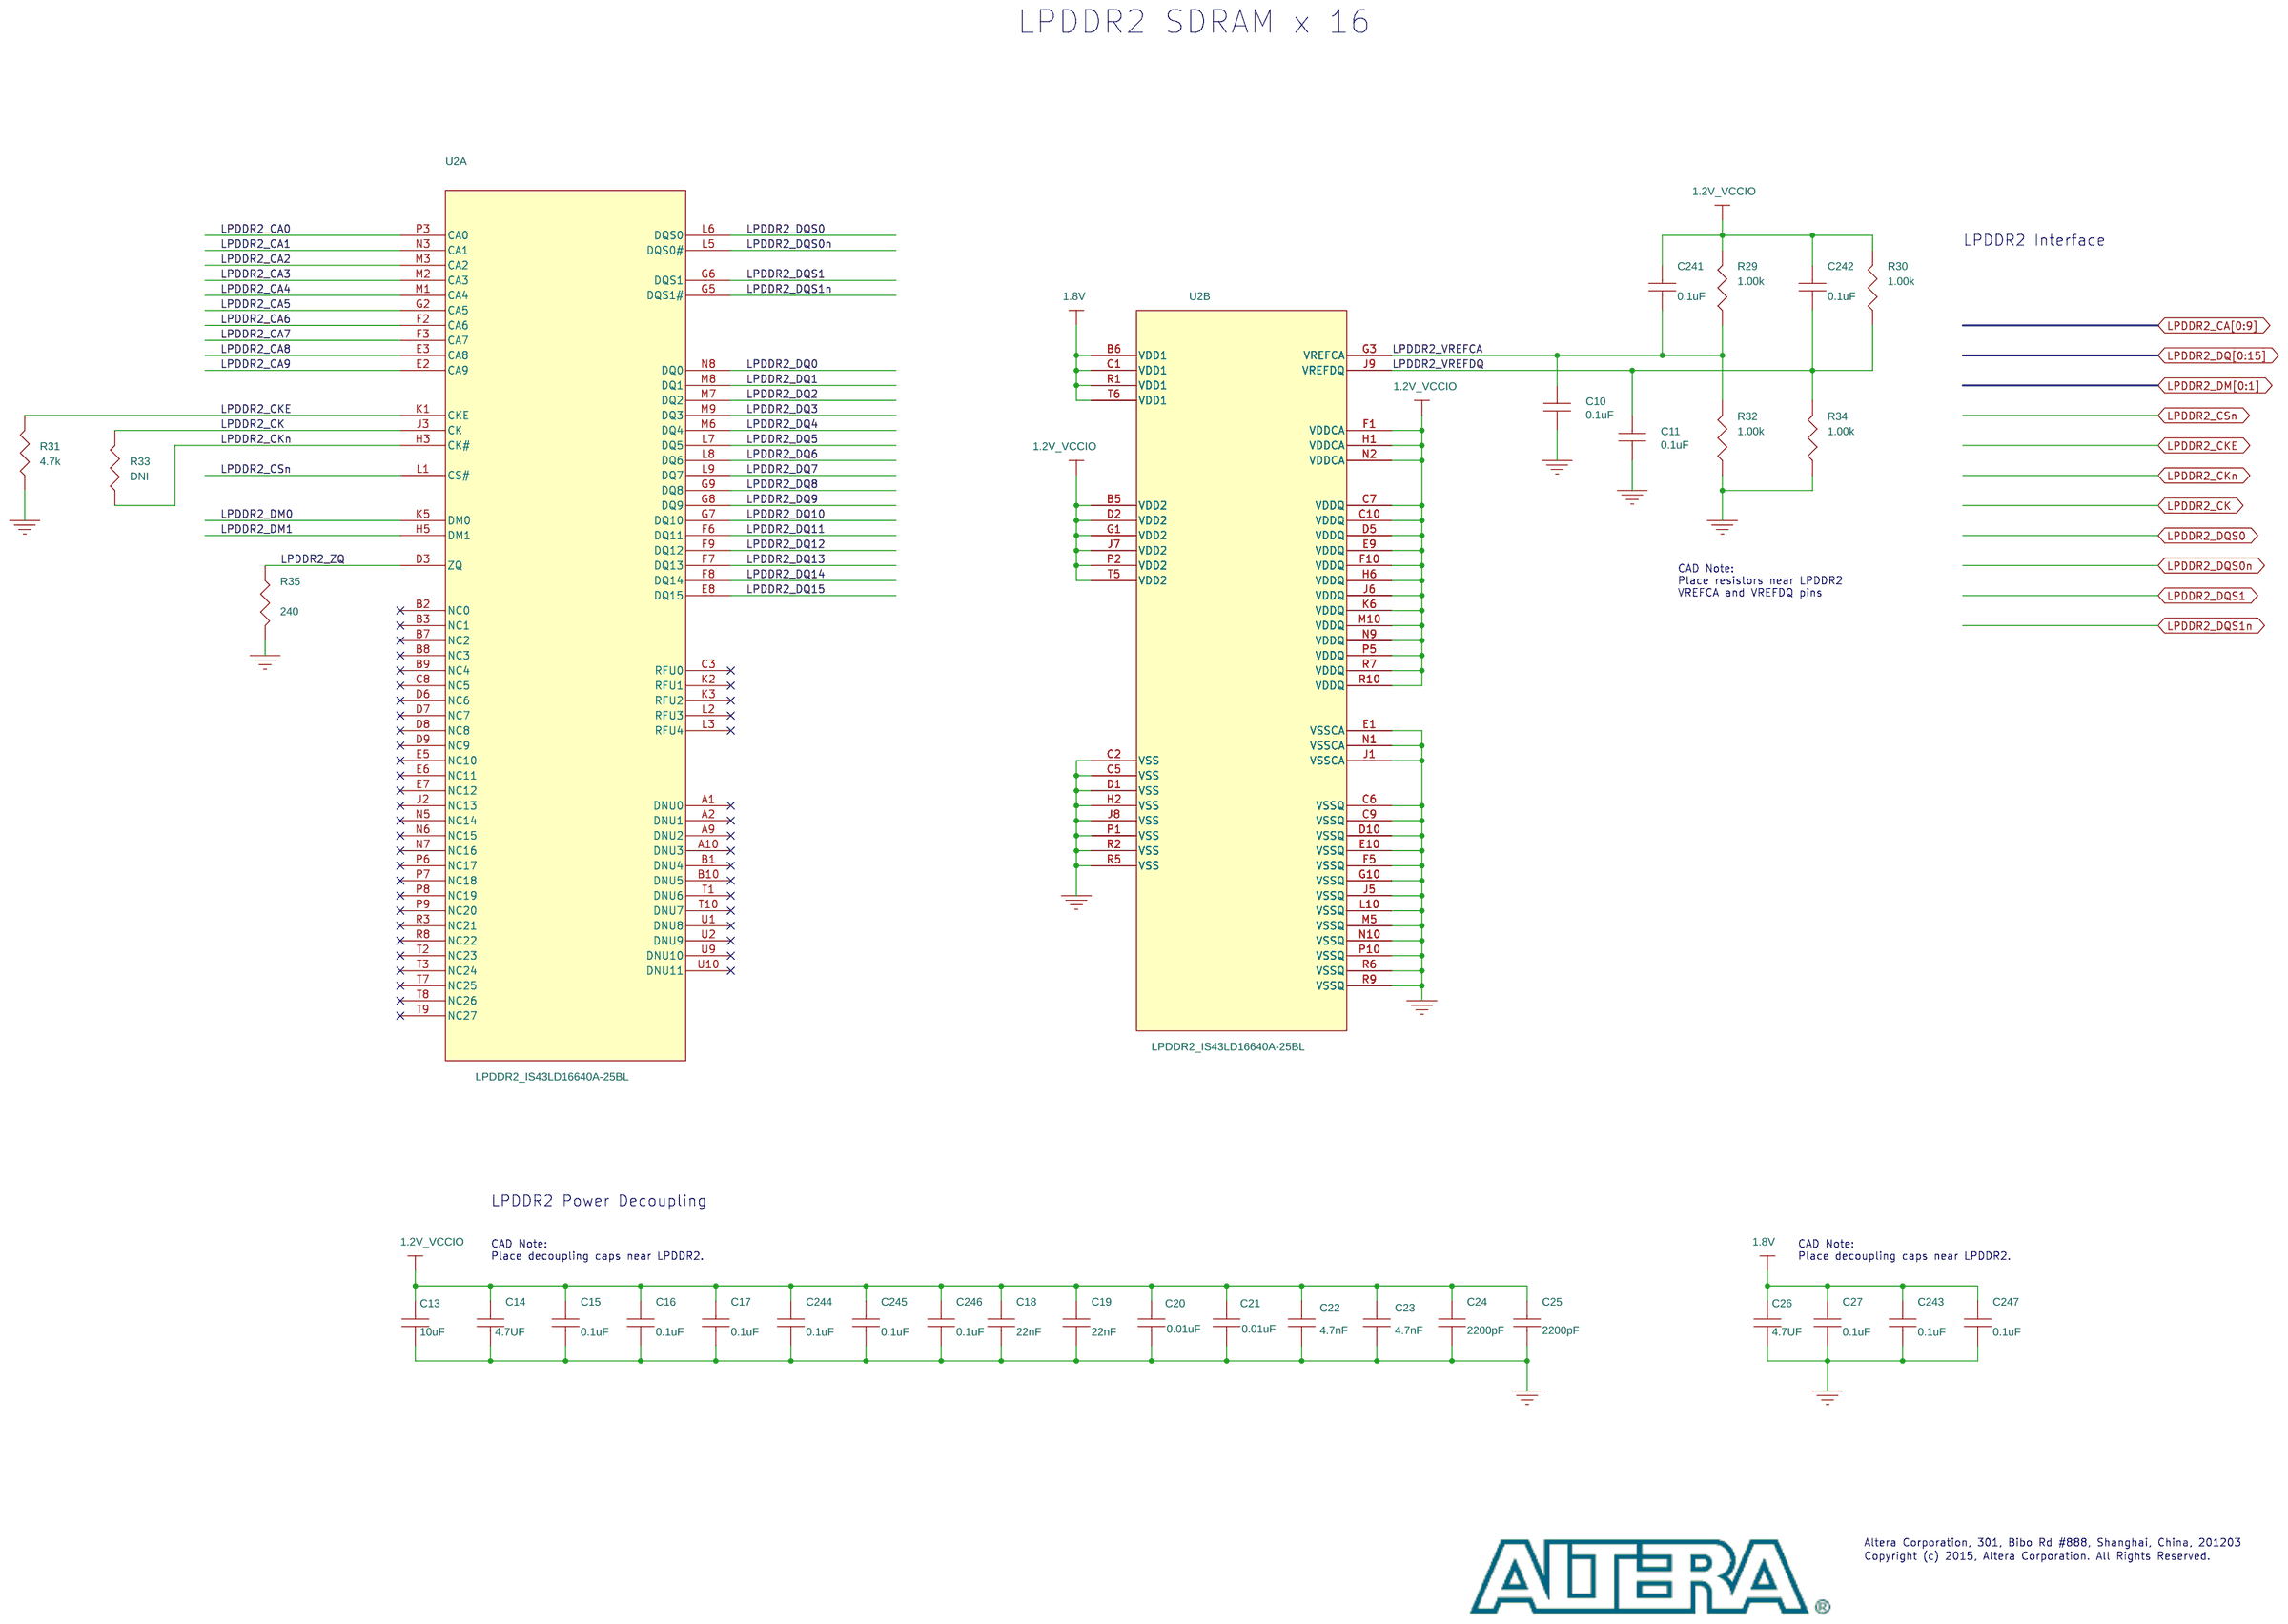
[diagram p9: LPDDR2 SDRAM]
11 MIPI CSI-2 Tx D-PHY LI-USB3: size A3
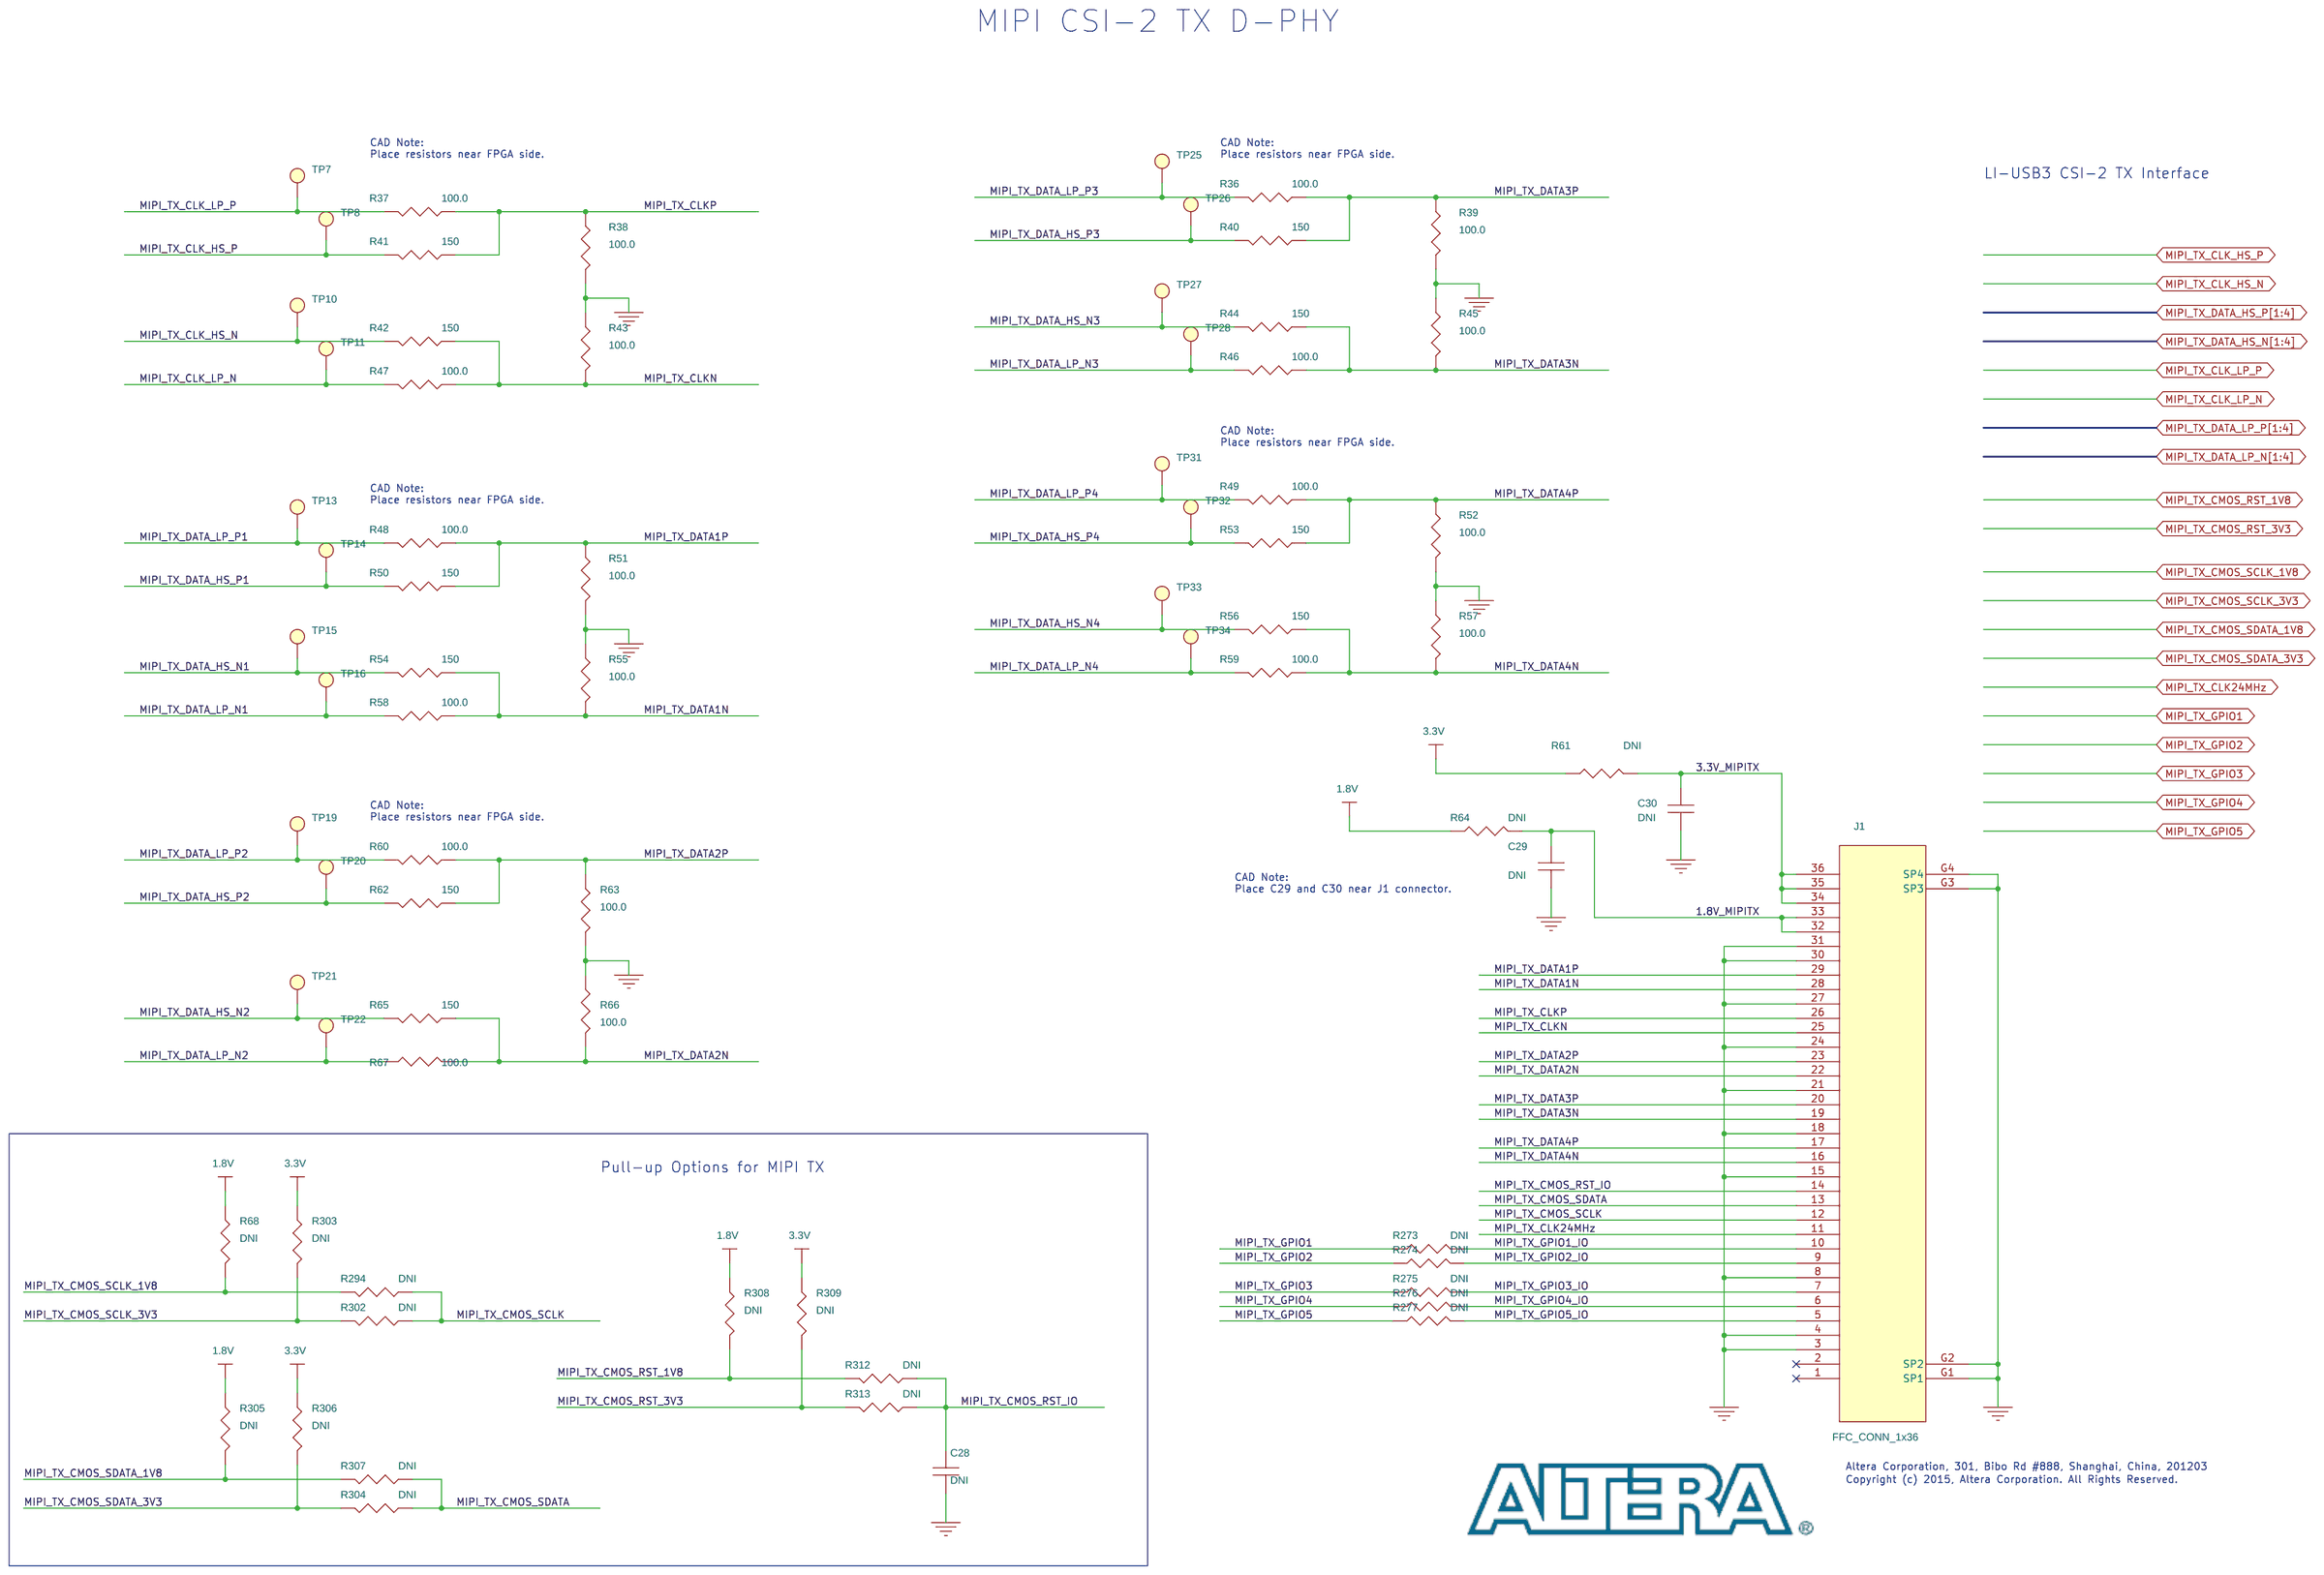
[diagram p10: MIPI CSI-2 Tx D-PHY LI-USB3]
12 MIPI CSI-2 Rx D-PHY OV10640: size A3
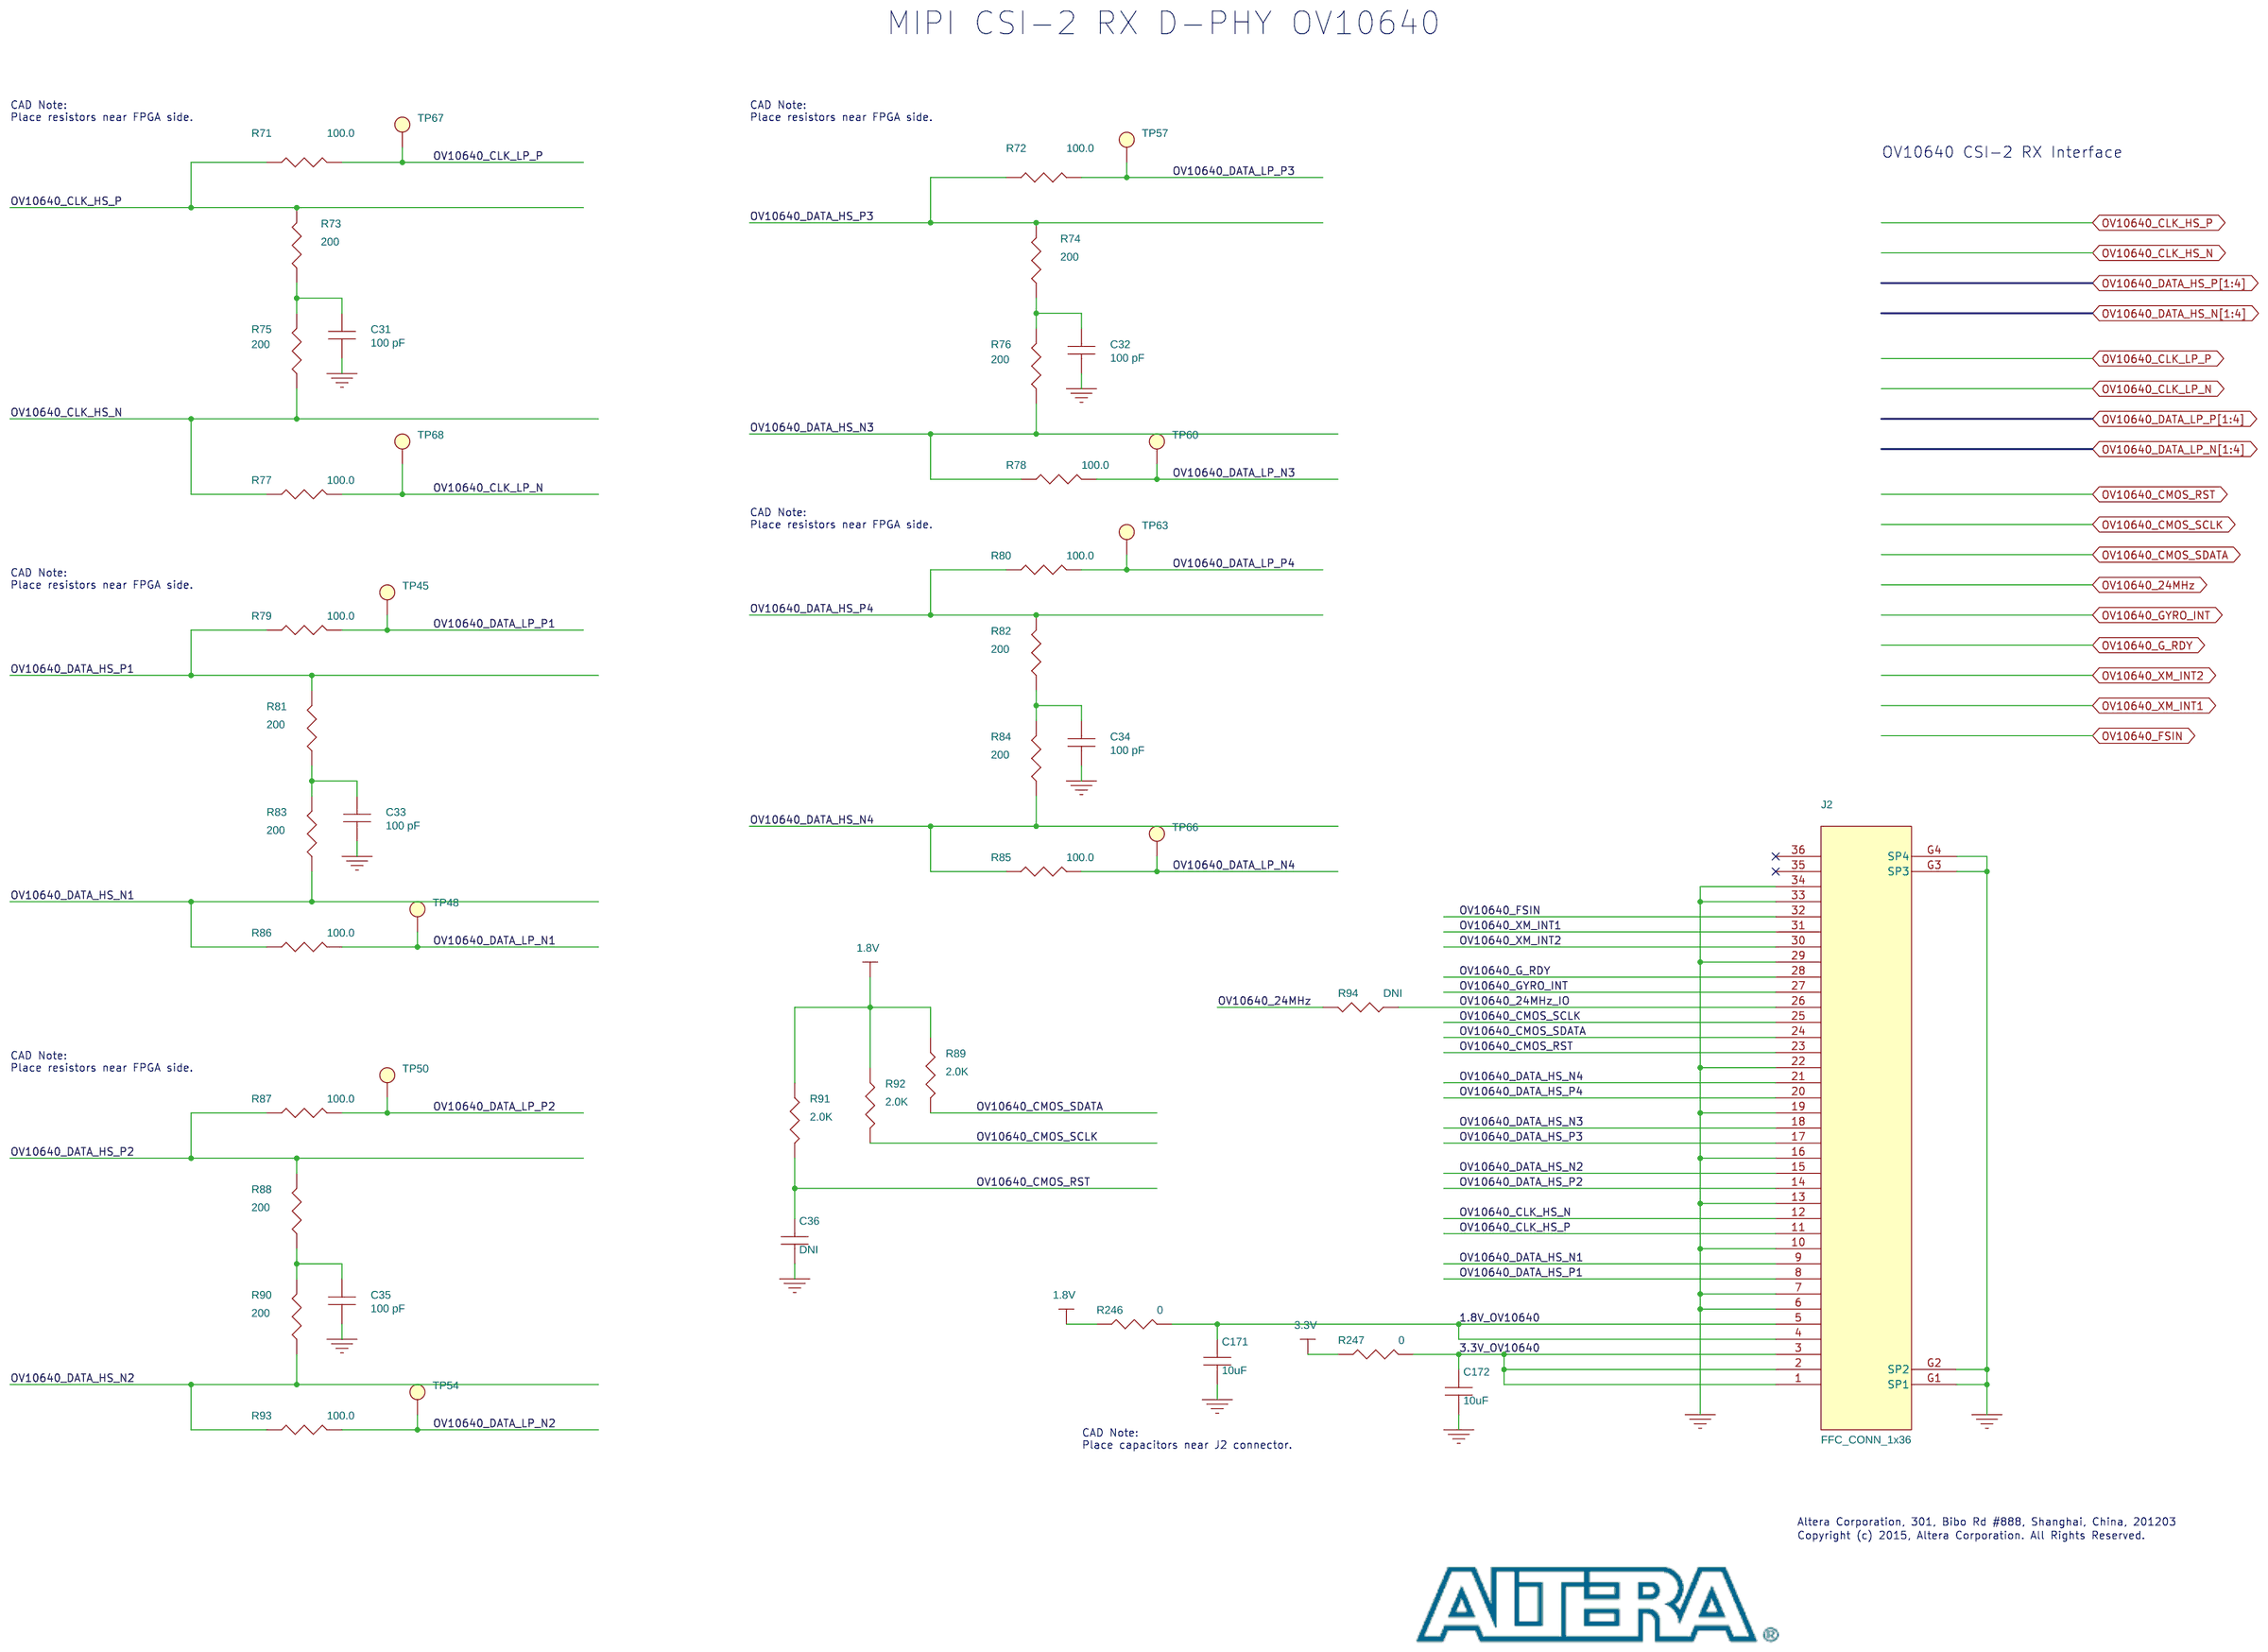
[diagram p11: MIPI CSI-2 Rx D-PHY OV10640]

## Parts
sheet LPDDR2 SDRAM
C10  0.1uF  [0402]
C11  0.1uF  [0402]
C13  10uF  [0603]
C14  4.7UF  [0402]
C15  0.1uF  [0402]
C16  0.1uF  [0402]
C17  0.1uF  [0402]
C18  22nF  [0402]
C19  22nF  [0402]
C20  0.01uF  [0402]
C21  0.01uF  [0402]
C22  4.7nF  [0402]
C23  4.7nF  [0402]
C24  2200pF  [0402]
C25  2200pF  [0402]
C26  4.7UF  [0402]
C27  0.1uF  [0402]
C241  0.1uF  [0402]
C242  0.1uF  [0402]
C243  0.1uF  [0402]
C244  0.1uF  [0402]
C245  0.1uF  [0402]
C246  0.1uF  [0402]
C247  0.1uF  [0402]
R29  1.00k  [0402]
R30  1.00k  [0402]
R31  4.7k  [0402]
R32  1.00k  [0402]
R33  DNI  [0402]
R34  1.00k  [0402]
R35  240  [0402]
U2  LPDDR2_IS43LD16640A-25BL  [FBGA134]  (sections A,B)
sheet MAX 10 Banks 1 & 2
C1  0.1uF  [0402]
C3  0.1uF  [0402]
R1  1.00k  [0402]
R2  1.00k  [0402]
sheet MAX 10 Banks 5 & 6
C4  0.1uF  [0402]
C6  0.1uF  [0402]
C8  0.1uF  [0402]
C9  0.1uF  [0402]
R7  47.5  [0402]
R8  47.5  [0402]
R9  1.00k  [0402]
R10  1.00k  [0402]
R11  1.00k  [0402]
R12  1.00k  [0402]
sheet MAX 10 Banks 7 & 8
R250  0  [0402]
sheet MAX 10 Clocks
R17  200  [0402]
R18  100.0  [0402]
R19  200  [0402]
R20  100.0  [0402]
R270  0  [0402]
R271  DNI  [0402]
sheet MAX 10 Configuration
R21  10.0K  [0402]
R22  DNI  [0402]
R23  1.00k  [0402]
R24  10.0K  [0402]
R25  10.0K  [0402]
R27  10.0K  [0402]
R28  10.0K  [0402]
R314  22.0  [0402]
U1  10M50DAF484  [F484]  (sections A,B,C,D,E,F,G,H)
sheet MIPI CSI-2 Rx D-PHY OV10640
C31  100 pF  [0402]
C32  100 pF  [0402]
C33  100 pF  [0402]
C34  100 pF  [0402]
C35  100 pF  [0402]
C36  DNI  [C0402_BGA]
C171  10uF  [0603]
C172  10uF  [0603]
J2  FFC_CONN_1x36  [52559-3652]
R71  100.0  [0402]
R72  100.0  [0402]
R73  200  [0402]
R74  200  [0402]
R75  200  [0402]
R76  200  [0402]
R77  100.0  [0402]
R78  100.0  [0402]
R79  100.0  [0402]
R80  100.0  [0402]
R81  200  [0402]
R82  200  [0402]
R83  200  [0402]
R84  200  [0402]
R85  100.0  [0402]
R86  100.0  [0402]
R87  100.0  [0402]
R88  200  [0402]
R89  2.0K  [0402]
R90  200  [0402]
R91  2.0K  [0402]
R92  2.0K  [0402]
R93  100.0  [0402]
R94  DNI  [0402]
R246  0  [0603]
R247  0  [0603]
TP45  T POINT R  [Test_Pad_SMT_10mil]
TP48  T POINT R  [Test_Pad_SMT_10mil]
TP50  T POINT R  [Test_Pad_SMT_10mil]
TP54  T POINT R  [Test_Pad_SMT_10mil]
TP57  T POINT R  [Test_Pad_SMT_10mil]
TP60  T POINT R  [Test_Pad_SMT_10mil]
TP63  T POINT R  [Test_Pad_SMT_10mil]
TP66  T POINT R  [Test_Pad_SMT_10mil]
TP67  T POINT R  [Test_Pad_SMT_10mil]
TP68  T POINT R  [Test_Pad_SMT_10mil]
sheet MIPI CSI-2 Tx D-PHY LI-USB3
C28  DNI  [C0402_BGA]
C29  DNI  [0603]
C30  DNI  [0603]
J1  FFC_CONN_1x36  [52559-3652]
R36  100.0  [0402]
R37  100.0  [0402]
R38  100.0  [0402]
R39  100.0  [0402]
R40  150  [0402]
R41  150  [0402]
R42  150  [0402]
R43  100.0  [0402]
R44  150  [0402]
R45  100.0  [0402]
R46  100.0  [0402]
R47  100.0  [0402]
R48  100.0  [0402]
R49  100.0  [0402]
R50  150  [0402]
R51  100.0  [0402]
R52  100.0  [0402]
R53  150  [0402]
R54  150  [0402]
R55  100.0  [0402]
R56  150  [0402]
R57  100.0  [0402]
R58  100.0  [0402]
R59  100.0  [0402]
R60  100.0  [0402]
R61  DNI  [0402]
R62  150  [0402]
R63  100.0  [0402]
R64  DNI  [0402]
R65  150  [0402]
R66  100.0  [0402]
R67  100.0  [0402]
R68  DNI  [0402]
R273  DNI  [0402]
R274  DNI  [0402]
R275  DNI  [0402]
R276  DNI  [0402]
R277  DNI  [0402]
R294  DNI  [0402]
R302  DNI  [0402]
R303  DNI  [0402]
R304  DNI  [0402]
R305  DNI  [0402]
R306  DNI  [0402]
R307  DNI  [0402]
R308  DNI  [0402]
R309  DNI  [0402]
R312  DNI  [0402]
R313  DNI  [0402]
TP7  T POINT R  [Test_Pad_SMT_10mil]
TP8  T POINT R  [Test_Pad_SMT_10mil]
TP10  T POINT R  [Test_Pad_SMT_10mil]
TP11  T POINT R  [Test_Pad_SMT_10mil]
TP13  T POINT R  [Test_Pad_SMT_10mil]
TP14  T POINT R  [Test_Pad_SMT_10mil]
TP15  T POINT R  [Test_Pad_SMT_10mil]
TP16  T POINT R  [Test_Pad_SMT_10mil]
TP19  T POINT R  [Test_Pad_SMT_10mil]
TP20  T POINT R  [Test_Pad_SMT_10mil]
TP21  T POINT R  [Test_Pad_SMT_10mil]
TP22  T POINT R  [Test_Pad_SMT_10mil]
TP25  T POINT R  [Test_Pad_SMT_10mil]
TP26  T POINT R  [Test_Pad_SMT_10mil]
TP27  T POINT R  [Test_Pad_SMT_10mil]
TP28  T POINT R  [Test_Pad_SMT_10mil]
TP31  T POINT R  [Test_Pad_SMT_10mil]
TP32  T POINT R  [Test_Pad_SMT_10mil]
TP33  T POINT R  [Test_Pad_SMT_10mil]
TP34  T POINT R  [Test_Pad_SMT_10mil]

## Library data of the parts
C1 C3 C4 C6 C8-C11 C15-C17 C27 C241-C247 = Cap_0.1UF_+_-10%_10V_0402
C13 C171 C172 = CAP: CAP - CERAMIC, 10UF, 6.3V, +/-20%, X5R, 0603 SMD; AGILE_LINK: http://sj-agile9app/Agile/PLMServlet?action=OpenEmailObject&classid=10000&objid=260383822; Item Num: P03-16323R; LIFECYCLE_PHASE: Active; Lead Free Status: Lead Free; MFR_LIFECYCLE: Active; Manufacturer: Panasonic; Manufacturer Part Num: ECJ-1VB0J106M; Num Pins: 2; PART_SUBCLASS: CAPACITORS; RATED_VOLTAGE: 6.3V; RoHS Compliant: RoHS Compliant; TOLERANCE: +/-20%
C14 C26 = Cap_4.7uF_10%_6.3V_X5R_0402
C18 C19 = Cap_22NF_10%_16V_0402: CAP 22000PF 16V CERAMIC X7R 0402; Item Num: P03-15013R; Manufacturer: Panasonic; Manufacturer Part Num: ECJ-0EB1C223K
C20 C21 = CAP_0.01UF_16V_X7R_0402: Manufacturer Part Num: GRM155R71C103KA01D
C22 C23 = Cap_4.7nF_10%_50V_0402: CAP 4700PF 25V CERAMIC 0402 SMD ±10% X7R; Item Num: P03-16476R; Manufacturer: Panasonic; Manufacturer Part Num: ECJ-0EB1E472K
C24 C25 = Cap_2200PF_10%_50V_0402: CAP, CERAMIC, 2200PF, 0402, 10%, 50VDC, X7R; Item Num: P03-15015R; Manufacturer: Panasonic; Manufacturer Part Num: ECJ-0EB1H222K
R1 R2 R9-R12 R22 R23 R29 R30 R32 R34 = RESISTOR: RES,1.00K OHMS,1.0%,1/16W,0402; Item Num: P02-11372R; Lead Free Status: No; Manufacturer: Panasonic; Manufacturer Part Num: ERJ-2RKF1001X; Num Pins: 2; Part Class: Resistors
R31 R33 = RES_4.7k_OHM_5%_1_16W_0402: RES - 4.7K OHMS, 5%, 1/16W,0402
R35 = RESISTOR: RES - 240 OHM, 1/16W, 1%, 0402 SMD; Item Num: P02-15995R; LIFECYCLE_PHASE: Active; Lead Free Status: Lead Free; MFR_LIFECYCLE: Active; Manufacturer: Panasonic; Manufacturer Part Num: ERJ-2RKF2400X; Num Pins: 2; PART_SUBCLASS: RESISTORS; RoHS Compliant: RoHS Compliant
U2 = LPDDR2_IS43LD16640A-3BL_2: IC -  MOBILE LPDDR2 S4 SDRAM, 1GB (64M X 16), 400MHZ; Item Num: P14-27622R; Manufacturer: ISSI; Manufacturer Part Num: IS43LD16640A-25BL
R7 R8 = RESISTOR: RES, 47.5 OHMS, 1%, 1/16W, 0402; Item Num: P02-14100R; Lead Free Status: No; Manufacturer: Panasonic; Manufacturer Part Num: ERJ-2RKF47R5X; Num Pins: 2; Part Class: Resistors
R250 R270 = RESISTOR: RES ZERO OHM 1/16W 5% 0402 SMD; Altera Part No.: P02-14020R; Item Num: P02-14020R; Lead Free Status: No; Manufacturer: Panasonic; Manufacturer Part Num: ERJ-2GE0R00X; Num Pins: 2; Part Class: RESISTORS; RoHS Compliant: Yes; Tolerance: 5%
R17 R19 R73-R76 R81-R84 R88 R90 = RESISTOR: RES,200 OHMS,1.0%,1/16W,0402; Item Num: P02-10716R; Lead Free Status: Yes; Manufacturer: Panasonic; Manufacturer Part Num: ERJ-2RKF2000X; Num Pins: 2; Part Class: Resistors; Price: 0; RoHS Compliant: Yes
R18 R20 R36-R39 R43 R45-R49 R51 R52 R55 R57-R60 R63 R66 R67 R71 R72 R77-R80 R85-R87 R93 = RES_100_OHM_1.0%_1_16W_0402: RES,100OHMS, 1.0%, 1/16W, 0402
R61 R64 R94 R271 R273-R277 R294 R302 R304 R307 R312 R313 = RESISTOR: RES ZERO OHM 1/16W 5% 0402 SMD; Altera Part No.: P02-14020R; Item Num: P02-14020R; Lead Free Status: No; Manufacturer: Panasonic; Manufacturer Part Num: ERJ-2GE0R00X; Num Pins: 2; Part Class: RESISTORS; Price: 0; RoHS Compliant: Yes; Tolerance: 5%
R21 R24 R25 R27 R28 = RESISTOR: RES,10.0K OHMS,1.0%,1/16W, 0402; AGILE_LINK: http://sj-agile9app/Agile/PLMServlet?action=OpenEmailObject&classid=10000&objid=146548997; Item Num: P02-11364R; LIFECYCLE_PHASE: Active; Lead Free Status: No; MFR_LIFECYCLE: Active; Manufacturer: Panasonic; Manufacturer Part Num: ERJ-2RKF1002X; Num Pins: 2; PART_SUBCLASS: RESISTORS; POWER: 1/16W; RoHS Compliant: Yes; TOLERANCE: +/-1%
R314 = RESISTOR: RES - 22.0 OHM, 1/16W, 1%, 0402 SMD; Item Num: P02-16269R; Lead Free Status: Yes; Manufacturer: Panasonic; Manufacturer Part Num: ERJ-2RKF22R0X; Num Pins: 2; Part Class: Resistors; Price: 0
U1 = 10M50DAF484_v2.0_4.5: IC - MAX 10 FPGA, 10M50DAF484C6GES, 50K LES, F484 BGA, LEADFREE, ENGINEERING SAMPLE; Item Num: P01-17977R; Manufacturer: Altera Corporation; Manufacturer Part Num: 10M50DAF484C6GES; Part Class: Regulators; RoHS Compliant: Yes
C31-C35 = Cap_0.1UF_+_-10%_10V_0402: CAP, CERAMIC, 100PF, 10%, 50V, 0402, X7R; Item Num: P03-15133R; Manufacturer Part Num: ECJ-0EB1H101K
C28 C36 = CAP_1.0UF_10%_10V_0402
J1 J2 = FCC_CONN_1: CONN FFC VERT 36POS 0.50MM SMD; Item Num: P23-38694R
R89 R91 R92 = RES_2.0K_OHM_1_16W_1%_0402_SMD
R246 R247 = RESISTOR: RES - 0 OHM, 5% 0603 1/10W; Altera Part No.: P02-14007R; Item Num: P02-14007R; Lead Free Status: No; Manufacturer: Panasonic; Manufacturer Part Num: ERJ-3GEY0R00V; Num Pins: 2; Part Class: RESISTORS; RoHS Compliant: Yes; Tolerance: 5%
TP7 TP8 TP10 TP11 TP13-TP16 TP19-TP22 TP25-TP28 TP31-TP34 TP45 TP48 TP50 TP54 TP57 TP60 TP63 TP66-TP68 = T_POINT_R
C29 C30 = CAP: CAP - CERAMIC, 10UF, 6.3V, +/-20%, X5R, 0603 SMD; AGILE_LINK: http://sj-agile9app/Agile/PLMServlet?action=OpenEmailObject&classid=10000&objid=260383822; CAPACITANCE: 10uF; Item Num: P03-16323R; LIFECYCLE_PHASE: Active; Lead Free Status: Lead Free; MFR_LIFECYCLE: Active; Manufacturer: Panasonic; Manufacturer Part Num: ECJ-1VB0J106M; Num Pins: 2; PART_SUBCLASS: CAPACITORS; RATED_VOLTAGE: 6.3V; RoHS Compliant: RoHS Compliant; TOLERANCE: +/-20%
R40-R42 R44 R50 R53 R54 R56 R62 R65 = R: RES 150 OHM 1% 1/16W 0402 SMD; Item Num: P02-15855R; Lead Free Status: No; Manufacturer: Panasonic; Manufacturer Part Num: ERJ-2RKF1500X; Num Pins: 2; Part Class: Resistors; Price: 0; RoHS Compliant: Yes
R68 R303 R305 R306 R308 R309 = RES_2.0K_OHM_1_16W_1%_0402_SMD: RES 2.2K OHM 1/16W 5% 0402 SMD; Item Num: P02-14027R; Manufacturer Part Num: ERJ-2GEJ222X

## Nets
1.2V_VCCIO: C4.1 C6.1 C13.1 C14.1 C15.1 C16.1 C17.1 C18.1 C19.1 C20.1 C21.1 C22.1 C23.1 C24.1 C25.1 C241.1 C242.1 C244.1 C245.1 C246.1 R7.1 R9.2 R10.2 R29.2 R30.2 U2.B5(VDD2) U2.C7(VDDQ) U2.C10(VDDQ) U2.D2(VDD2) U2.D5(VDDQ) U2.E9(VDDQ) U2.F1(VDDCA) U2.F10(VDDQ) U2.G1(VDD2) U2.H1(VDDCA) U2.H6(VDDQ) U2.J6(VDDQ) U2.J7(VDD2) U2.K6(VDDQ) U2.M10(VDDQ) U2.N2(VDDCA) U2.N9(VDDQ) U2.P2(VDD2) U2.P5(VDDQ) U2.R7(VDDQ) U2.R10(VDDQ) U2.T5(VDD2) ; also on sheet 18 22 23 24
1.8V: C26.1 C27.1 C243.1 C247.1 R1.2 R64.1 R68.1 R89.1 R91.1 R92.1 R246.1 R305.1 R308.1 U2.B6(VDD1) U2.C1(VDD1) U2.R1(VDD1) U2.T6(VDD1) ; also on sheet 14 19 20 21 22 23 24
1.8V_MIPITX: C29.1 J1.32 J1.33 R64.2
1.8V_OV10640: C171.1 J2.4 J2.5 R246.2
2.5V: R21.1 R24.1 R25.1 ; also on sheet 16 17 18 19 21 22 23 24
3.3V: R27.1 R28.1 R61.1 R247.1 R303.1 R306.1 R309.1 ; also on sheet 13 14 15 16 17 18 19 20 22 23 24 25
3.3V_MIPITX: C30.1 J1.34 J1.35 J1.36 R61.2
3.3V_OV10640: C172.1 J2.1 J2.2 J2.3 R247.2
GND: C1.2 C3.2 C8.2 C9.2 C10.2 C11.2 C13.2 C14.2 C15.2 C16.2 C17.2 C18.2 C19.2 C20.2 C21.2 C22.2 C23.2 C24.2 C25.2 C26.2 C27.2 C28.2 C29.2 C30.2 C31.2 C32.2 C33.2 C34.2 C35.2 C36.2 C171.2 C172.2 C243.2 C244.2 C245.2 C246.2 C247.2 J1.3 J1.4 J1.8 J1.15 J1.18 J1.21 J1.24 J1.27 J1.30 J1.31 J1.G1(SP1) J1.G2(SP2) J1.G3(SP3) J1.G4(SP4) J2.6 J2.7 J2.10 J2.13 J2.16 J2.19 J2.22 J2.29 J2.33 J2.34 J2.G1(SP1) J2.G2(SP2) J2.G3(SP3) J2.G4(SP4) R2.1 R8.1 R11.1 R12.1 R18.1 R20.1 R22.1 R23.1 R31.1 R32.1 R34.1 R35.2 R38.2 R39.2 R43.1 R45.1 R51.2 R52.2 R55.1 R57.1 R63.2 R66.1 U1.B20(DIFFIO_RX_R62P) U1.B21(DIFFIO_RX_R60N) U1.C20(DIFFIO_RX_R56P) U1.C21(TBD6) U1.D19(DIFFIO_RX_R56N) U1.E6(DIFFIO_RX_T52N/PLL_T_CLKOUTN) U1.E17(DIFFIO_RX_R59N) U1.E19(DIFFIO_RX_R53P) U1.E20(DIFFIO_RX_R54N) U1.F17(DIFFIO_RX_R59P) U1.F18(DIFFIO_RX_R53N) U1.F19(DIFFIO_RX_R54P) U1.F20(DIFFIO_RX_R48N) U1.F21(DIFFIO_RX_R48P) U1.G17(DIFFIO_RX_R69N/PLL_R_CLKOUTN) U1.G19(DIFFIO_RX_R42N) U1.G20(DIFFIO_RX_R42P) U1.H11(DIFFIO_RX_T40N/CLK5N) U1.H17(DIFFIO_RX_R69P/PLL_R_CLKOUTP) U1.J8(DIFFIO_RX_L3N/ADC1IN3) U1.J9(DIFFIO_RX_L3P/ADC1IN4) U1.J20(DIFFIO_RX_R64P/DQ3R) U1.K4(DIFFIO_RX_L8N/ADC2IN7) U1.K5(DIFFIO_RX_L7N/ADC1IN7) U1.K6(DIFFIO_RX_L7P/ADC1IN8) U1.L19(DIFFIO_RX_R52P/DQ2R) U1.L22(DIFFIO_RX_R34N) U1.M8(DIFFIO_RX_L36N/CLK1N) U1.M21(DIFFIO_RX_R34P) U1.M22(DIFFIO_RX_R35N) U1.N4(DIFFIO_RX_L28N/CLK0N) U1.N15(DIFFIO_RX_R38N/CLK2N) U1.N21(DIFFIO_RX_R35P) U1.P3(DIFFIO_RX_L38N/DPCLK0) U1.P18(DIFFIO_RX_R32N/DQSN1R) U1.P19(DIFFIO_RX_R33P/DQ1R) U1.P20(DIFFIO_RX_R33N/DQ1R) U1.R3(DIFFIO_RX_L38P/DPCLK1) U1.R22(TBD5) U1.T5(DIFFIO_RX_L59N/PLL_L_CLKOUTN) U1.T6(DIFFIO_RX_L59P/PLL_L_CLKOUTP) U1.T20(DIFFIO_RX_R28P/DQ1R) U1.U21(DIFFIO_RX_R29P) U1.U22(DIFFIO_RX_R29N) U1.V18(DIFFIO_RX_R19P) U1.V20(DIFFIO_RX_R23P) U2.C2(VSS) U2.C5(VSS) U2.C6(VSSQ) U2.C9(VSSQ) U2.D1(VSS) U2.D10(VSSQ) U2.E1(VSSCA) U2.E10(VSSQ) U2.F5(VSSQ) U2.G10(VSSQ) U2.H2(VSS) U2.J1(VSSCA) U2.J5(VSSQ) U2.J8(VSS) U2.L10(VSSQ) U2.M5(VSSQ) U2.N1(VSSCA) U2.N10(VSSQ) U2.P1(VSS) U2.P10(VSSQ) U2.R2(VSS) U2.R5(VSS) U2.R6(VSSQ) U2.R9(VSSQ) ; also on sheet 13 14 15 16 17 18 19 20 21 22 23 24 25
CLK24M: U1.M9(DIFFIO_RX_L36P/CLK1P) ; also on sheet 19
CLK50M_MAX10: U1.J10(DIFFIO_RX_T40P/CLK5P) ; also on sheet 19
CLK100M_LPDDR2: U1.E10(DIFFIO_RX_T38N/CLK4N) ; also on sheet 19
CLK100M_LPDDR2_BK: R17.2 ; also on sheet 19
CLK100M_LPDDR2_BKDIV: R17.1 R18.2 U1.N14(DIFFIO_RX_R38P/CLK2P)
CLK125M: R19.2 ; also on sheet 19
CLK125M_DIV_R: R19.1 R20.2 R270.1
CLKOUT_LVDS_N: U1.W17(DIFFIO_TX_RX_B57N/PLL_B_CLKOUTN) ; also on sheet 17
CLKOUT_LVDS_P: U1.V17(DIFFIO_TX_RX_B57P/PLL_B_CLKOUTP) ; also on sheet 17
FLASH_CLK: U1.A9(DIFFIO_RX_T31P) ; also on sheet 25
FLASH_CSn: U1.A8(DIFFIO_RX_T29N) ; also on sheet 25
FLASH_D0: U1.C9(DIFFIO_RX_T30N) ; also on sheet 25
FLASH_D1: U1.C10(DIFFIO_RX_T26N) ; also on sheet 25
FLASH_D2: U1.C11(DIFFIO_RX_T26P) ; also on sheet 25
FLASH_D3: U1.A7(DIFFIO_RX_T29P) ; also on sheet 25
FLASH_RESETn: R250.1 ; also on sheet 15 25
FLASH_RESETn_MAX10: R250.2 U1.B8(DIFFIO_RX_T31N)
HDMI_HSYNC: U1.H13(DIFFIO_RX_T22P) ; also on sheet 14
HDMI_INTR: U1.A18(DIFFIO_RX_T10P) ; also on sheet 14
HDMI_SCL: U1.C16(DIFFIO_RX_T15P) ; also on sheet 14
HDMI_SDA: U1.B17(DIFFIO_RX_T7N) ; also on sheet 14
HDMI_VIDEO_CLK: U1.D6(DIFFIO_RX_T52P/PLL_T_CLKOUTP) ; also on sheet 14
HDMI_VIDEO_DATA_EN: U1.J13(DIFFIO_RX_T17N) ; also on sheet 14
HDMI_VIDEO_DIN0: U1.J12(DIFFIO_RX_T22N) ; also on sheet 14
HDMI_VIDEO_DIN1: U1.D13(DIFFIO_RX_T21N) ; also on sheet 14
HDMI_VIDEO_DIN2: U1.E12(DIFFIO_RX_T21P) ; also on sheet 14
HDMI_VIDEO_DIN3: U1.E13(DIFFIO_RX_T20N) ; also on sheet 14
HDMI_VIDEO_DIN4: U1.D12(DIFFIO_RX_T24N) ; also on sheet 14
HDMI_VIDEO_DIN5: U1.B16(DIFFIO_RX_T16P) ; also on sheet 14
HDMI_VIDEO_DIN6: U1.A16(DIFFIO_RX_T16N) ; also on sheet 14
HDMI_VIDEO_DIN7: U1.C15(DIFFIO_RX_T15N) ; also on sheet 14
HDMI_VIDEO_DIN8: U1.B14(DIFFIO_RX_T19N) ; also on sheet 14
HDMI_VIDEO_DIN9: U1.A14(DIFFIO_RX_T19P) ; also on sheet 14
HDMI_VIDEO_DIN10: U1.A13(DIFFIO_RX_T23P) ; also on sheet 14
HDMI_VIDEO_DIN11: U1.B12(DIFFIO_RX_T27P) ; also on sheet 14
HDMI_VIDEO_DIN12: U1.A12(DIFFIO_RX_T23N) ; also on sheet 14
HDMI_VIDEO_DIN13: U1.C12(DIFFIO_RX_T24P) ; also on sheet 14
HDMI_VIDEO_DIN14: U1.A11(DIFFIO_RX_T25P) ; also on sheet 14
HDMI_VIDEO_DIN15: U1.B11(DIFFIO_RX_T27N) ; also on sheet 14
HDMI_VIDEO_DIN16: U1.A10(DIFFIO_RX_T25N) ; also on sheet 14
HDMI_VIDEO_DIN17: U1.C14(DIFFIO_RX_T18P) ; also on sheet 14
HDMI_VIDEO_DIN18: U1.E14(DIFFIO_RX_T9N) ; also on sheet 14
HDMI_VIDEO_DIN19: U1.D14(DIFFIO_RX_T20P) ; also on sheet 14
HDMI_VIDEO_DIN20: U1.C13(DIFFIO_RX_T18N) ; also on sheet 14
HDMI_VIDEO_DIN21: U1.E15(DIFFIO_RX_T1N) ; also on sheet 14
HDMI_VIDEO_DIN22: U1.F15(DIFFIO_RX_T5N) ; also on sheet 14
HDMI_VIDEO_DIN23: U1.D15(DIFFIO_RX_T9P) ; also on sheet 14
HDMI_VSYNC: U1.H14(DIFFIO_RX_T17P) ; also on sheet 14
JTAG_SAFE: U1.K1(DIFFIO_RX_L25N) ; also on sheet 15
LPDDR2_CA0: U1.J22(DIFFIO_RX_R41P) U2.P3(CA0)
LPDDR2_CA1: U1.J21(DIFFIO_RX_R41N) U2.N3(CA1)
LPDDR2_CA2: U1.F22(DIFFIO_RX_R43N) U2.M3(CA2)
LPDDR2_CA3: U1.H21(DIFFIO_RX_R39N) U2.M2(CA3)
LPDDR2_CA4: U1.H22(DIFFIO_RX_R39P) U2.M1(CA4)
LPDDR2_CA5: U1.D22(DIFFIO_RX_R49P) U2.G2(CA5)
LPDDR2_CA6: U1.C22(DIFFIO_RX_R49N) U2.F2(CA6)
LPDDR2_CA7: U1.E22(DIFFIO_RX_R45P) U2.F3(CA7)
LPDDR2_CA8: U1.A21(DIFFIO_RX_R62N) U2.E3(CA8)
LPDDR2_CA9: U1.B22(DIFFIO_RX_R60P) U2.E2(CA9)
LPDDR2_CK: R33.2 U1.D18(DIFFIO_RX_R70P/CK_6) U2.J3(CK)
LPDDR2_CKE: R31.2 U1.E21(DIFFIO_RX_R45N) U2.K1(CKE)
LPDDR2_CKn: R33.1 U1.E18(DIFFIO_RX_R70N/CK#_6) U2.H3(CK#)
LPDDR2_CSn: U1.G22(DIFFIO_RX_R43P) U2.L1(CS#)
LPDDR2_DM0: U1.N19(DIFFIO_RX_R46N/DM2R) U2.K5(DM0)
LPDDR2_DM1: U1.J15(DIFFIO_RX_R61N/DM3R) U2.H5(DM1)
LPDDR2_DQ0: U1.N18(DIFFIO_RX_R46P/DQ2R) U2.N8(DQ0)
LPDDR2_DQ1: U1.N20(DIFFIO_RX_R47N/DQ2R) U2.M8(DQ1)
LPDDR2_DQ2: U1.M20(DIFFIO_RX_R47P/DQ2R) U2.M7(DQ2)
LPDDR2_DQ3: U1.M14(DIFFIO_RX_R44N/DQ2R) U2.M9(DQ3)
LPDDR2_DQ4: U1.M18(DIFFIO_RX_R51P/DQ2R) U2.M6(DQ4)
LPDDR2_DQ5: U1.M15(DIFFIO_RX_R44P/DQ2R) U2.L7(DQ5)
LPDDR2_DQ6: U1.L20(DIFFIO_RX_R52N/DQ2R) U2.L8(DQ6)
LPDDR2_DQ7: U1.L18(DIFFIO_RX_R51N/DQ2R) U2.L9(DQ7)
LPDDR2_DQ8: U1.K20(DIFFIO_RX_R58N/DQ3R) U2.G9(DQ8)
LPDDR2_DQ9: U1.K19(DIFFIO_RX_R58P/DQ3R) U2.G8(DQ9)
LPDDR2_DQ10: U1.K18(DIFFIO_RX_R57P/DQ3R) U2.G7(DQ10)
LPDDR2_DQ11: U1.H19(DIFFIO_RX_R63P/DQ3R) U2.F6(DQ11)
LPDDR2_DQ12: U1.H20(DIFFIO_RX_R64N/DQ3R) U2.F9(DQ12)
LPDDR2_DQ13: U1.H18(DIFFIO_RX_R63N/DQ3R) U2.F7(DQ13)
LPDDR2_DQ14: U1.J14(DIFFIO_RX_R61P/DQ3R) U2.F8(DQ14)
LPDDR2_DQ15: U1.J18(DIFFIO_RX_R57N/DQ3R) U2.E8(DQ15)
LPDDR2_DQS0: U1.L14(DIFFIO_RX_R50P/DPCLK3/DQS2R) U2.L6(DQS0)
LPDDR2_DQS0n: U1.L15(DIFFIO_RX_R50N/DPCLK2/DQSn2R) U2.L5(DQS0#)
LPDDR2_DQS1: U1.K14(DIFFIO_RX_R55P/DQS3R) U2.G6(DQS1)
LPDDR2_DQS1n: U1.K15(DIFFIO_RX_R55N/DQSN3R) U2.G5(DQS1#)
LPDDR2_VREFCA: C10.1 C241.2 R29.1 R32.2 U2.G3(VREFCA)
LPDDR2_VREFDQ: C11.1 C242.2 R30.1 R34.2 U2.J9(VREFDQ)
LPDDR2_ZQ: R35.1 U2.D3(ZQ)
MAX10_CONF_DONE: R28.2 U1.F8(DIFFIO_RX_T50N/CONF_DONE) ; also on sheet 15
MAX10_CONFIG_SEL: U1.H10(BOOT_SEL) ; also on sheet 18
MAX10_JTAG_TCK: R23.2 U1.G2(DIFFIO_RX_L17P/TCK) ; also on sheet 16
MAX10_JTAG_TDI: R25.2 U1.L4(DIFFIO_RX_L18N/TDI) ; also on sheet 16
MAX10_JTAG_TDO: R314.1 ; also on sheet 16
MAX10_JTAG_TDO_3V3: R314.2 U1.M5(DIFFIO_RX_L18P/TDO)
MAX10_JTAG_TMS: R24.2 U1.H2(DIFFIO_RX_L17N/TMS) ; also on sheet 16
MAX10_JTAGEN: R21.2 R22.2 U1.K9(DIFFIO_RX_L15P/JTAGEN) ; also on sheet 16
MAX10_nCONFIG: U1.H9(NCONFIG) ; also on sheet 18
MAX10_nSTATUS: R27.2 U1.G9(DIFFIO_RX_T50P/NSTATUS) ; also on sheet 15
MAX10_RDN: R8.2 U1.U17(DIFFIO_RX_R1N/RDN)
MAX10_RESETn: U1.D9(DIFFIO_RX_T42N/DEV_CLRN) ; also on sheet 18
MAX10_RUP: R7.2 U1.U18(DIFFIO_RX_R1P/RUP)
MIPI_TX_CLK24MHz: J1.11 ; also on sheet 19
MIPI_TX_CLK_HS_N: R42.2 TP10.1(TP) U1.R1(DIFFIO_RX_L60N)
MIPI_TX_CLK_HS_P: R41.2 TP8.1(TP) U1.R2(DIFFIO_RX_L60P)
MIPI_TX_CLK_LP_N: R47.2 TP11.1(TP) U1.Y1(DIFFIO_RX_B4N)
MIPI_TX_CLK_LP_P: R37.2 TP7.1(TP) U1.Y2(DIFFIO_RX_B4P)
MIPI_TX_CLKN: J1.25 R42.1 R43.2 R47.1
MIPI_TX_CLKP: J1.26 R37.1 R38.1 R41.1
MIPI_TX_CMOS_RST_1V8: R308.2 R312.2 U1.T3(DIFFIO_RX_L43N)
MIPI_TX_CMOS_RST_3V3: R309.2 R313.2 U1.B10(DIFFIO_RX_T30P)
MIPI_TX_CMOS_RST_IO: C28.1 J1.14 R312.1 R313.1
MIPI_TX_CMOS_SCLK: J1.12 R294.1 R302.1
MIPI_TX_CMOS_SCLK_1V8: R68.2 R294.2 U1.N3(DIFFIO_RX_L37N)
MIPI_TX_CMOS_SCLK_3V3: R302.2 R303.2 U1.J11(DIFFIO_RX_T28N)
MIPI_TX_CMOS_SDATA: J1.13 R304.1 R307.1
MIPI_TX_CMOS_SDATA_1V8: R305.2 R307.2 U1.N2(DIFFIO_RX_L37P)
MIPI_TX_CMOS_SDATA_3V3: R304.2 R306.2 U1.H12(DIFFIO_RX_T28P)
MIPI_TX_DATA1N: J1.28 R54.1 R55.2 R58.1
MIPI_TX_DATA1P: J1.29 R48.1 R50.1 R51.1
MIPI_TX_DATA2N: J1.22 R65.1 R66.2 R67.2
MIPI_TX_DATA2P: J1.23 R60.1 R62.1 R63.1
MIPI_TX_DATA3N: J1.19 R44.1 R45.2 R46.1
MIPI_TX_DATA3P: J1.20 R36.1 R39.1 R40.1
MIPI_TX_DATA4N: J1.16 R56.1 R57.2 R59.1
MIPI_TX_DATA4P: J1.17 R49.1 R52.1 R53.1
MIPI_TX_DATA_HS_N1: R54.2 TP15.1(TP) U1.P1(DIFFIO_RX_L42N)
MIPI_TX_DATA_HS_N2: R65.2 TP21.1(TP) U1.T1(DIFFIO_RX_L40N)
MIPI_TX_DATA_HS_N3: R44.2 TP27.1(TP) U1.U1(DIFFIO_RX_L44N)
MIPI_TX_DATA_HS_N4: R56.2 TP33.1(TP) U1.W1(DIFFIO_RX_L48N)
MIPI_TX_DATA_HS_P1: R50.2 TP14.1(TP) U1.N1(DIFFIO_RX_L42P)
MIPI_TX_DATA_HS_P2: R62.2 TP20.1(TP) U1.T2(DIFFIO_RX_L40P)
MIPI_TX_DATA_HS_P3: R40.2 TP26.1(TP) U1.V1(DIFFIO_RX_L44P)
MIPI_TX_DATA_HS_P4: R53.2 TP32.1(TP) U1.W2(DIFFIO_RX_L48P)
MIPI_TX_DATA_LP_N1: R58.2 TP16.1(TP) U1.V4(DIFFIO_RX_B2N)
MIPI_TX_DATA_LP_N2: R67.1 TP22.1(TP) U1.AB2(DIFFIO_RX_B12N)
MIPI_TX_DATA_LP_N3: R46.2 TP28.1(TP) U1.AA5(DIFFIO_RX_B17N)
MIPI_TX_DATA_LP_N4: R59.2 TP34.1(TP) U1.AB6(DIFFIO_RX_B19N)
MIPI_TX_DATA_LP_P1: R48.2 TP13.1(TP) U1.V5(DIFFIO_RX_B2P)
MIPI_TX_DATA_LP_P2: R60.2 TP19.1(TP) U1.AB3(DIFFIO_RX_B12P)
MIPI_TX_DATA_LP_P3: R36.2 TP25.1(TP) U1.AB5(DIFFIO_RX_B17P)
MIPI_TX_DATA_LP_P4: R49.2 TP31.1(TP) U1.AB7(DIFFIO_RX_B19P)
MIPI_TX_GPIO1: R273.1 U1.U3(DIFFIO_RX_L46N)
MIPI_TX_GPIO1_IO: J1.10 R273.2
MIPI_TX_GPIO2: R274.1 U1.U2(DIFFIO_RX_L43P)
MIPI_TX_GPIO2_IO: J1.9 R274.2
MIPI_TX_GPIO3: R275.1 U1.U4(DIFFIO_RX_L45N)
MIPI_TX_GPIO3_IO: J1.7 R275.2
MIPI_TX_GPIO4: R276.1 U1.U5(DIFFIO_RX_L45P)
MIPI_TX_GPIO4_IO: J1.6 R276.2
MIPI_TX_GPIO5: R277.1 U1.V3(DIFFIO_RX_L46P)
MIPI_TX_GPIO5_IO: J1.5 R277.2
OV5640_CAM_PWRON: U1.L2(DIFFIO_RX_L19P) ; also on sheet 13
OV5640_CAM_RESETB: U1.M4(DIFFIO_RX_L24N) ; also on sheet 13
OV5640_CLK_HS_N: U1.V9(DIFFIO_TX_RX_B18N/CLK6N) ; also on sheet 13
OV5640_CLK_HS_P: U1.V10(DIFFIO_TX_RX_B18P/CLK6P) ; also on sheet 13
OV5640_CLK_LP_N: U1.R14(DIFFIO_RX_R25N/DQ1R) ; also on sheet 13
OV5640_CLK_LP_P: U1.R15(DIFFIO_RX_R25P/DQ1R) ; also on sheet 13
OV5640_DATA_HS_N1: U1.AB12(DIFFIO_RX_B29N) ; also on sheet 13
OV5640_DATA_HS_N2: U1.AB10(DIFFIO_RX_B27N) ; also on sheet 13
OV5640_DATA_HS_P1: U1.AB13(DIFFIO_RX_B29P) ; also on sheet 13
OV5640_DATA_HS_P2: U1.AB11(DIFFIO_RX_B27P) ; also on sheet 13
OV5640_DATA_LP_N1: U1.W20(DIFFIO_RX_R21N) ; also on sheet 13
OV5640_DATA_LP_N2: U1.P14(DIFFIO_RX_R30N/DQ1R) ; also on sheet 13
OV5640_DATA_LP_P1: U1.W19(DIFFIO_RX_R21P) ; also on sheet 13
OV5640_DATA_LP_P2: U1.P15(DIFFIO_RX_R30P/DQ1R) ; also on sheet 13
OV5640_SDA: U1.L1(DIFFIO_RX_L25P) ; also on sheet 13
OV5640_SDC: U1.M3(DIFFIO_RX_L24P) ; also on sheet 13
OV10640_24MHz: R94.2 U1.N5(DIFFIO_RX_L28P/CLK0P)
OV10640_24MHz_IO: J2.26 R94.1
OV10640_CLK_HS_N: J2.12 R75.1 R77.1 U1.R11(DIFFIO_TX_RX_B20N/CLK7N)
OV10640_CLK_HS_P: J2.11 R71.1 R73.2 U1.P11(DIFFIO_TX_RX_B20P/CLK7P)
OV10640_CLK_LP_N: R77.2 TP68.1(TP) U1.T22(DIFFIO_RX_R26N)
OV10640_CLK_LP_P: R71.2 TP67.1(TP) U1.T21(DIFFIO_RX_R26P)
OV10640_CMOS_RST: C36.1 J2.23 R91.2 U1.P4(DIFFIO_RX_L29N)
OV10640_CMOS_SCLK: J2.25 R92.2 U1.P5(DIFFIO_RX_L29P)
OV10640_CMOS_SDATA: J2.24 R89.2 U1.N8(DIFFIO_RX_L41N)
OV10640_DATA_HS_N1: J2.9 R83.1 R86.1 U1.AB21(DIFFIO_RX_B50N)
OV10640_DATA_HS_N2: J2.15 R90.1 R93.1 U1.AB19(DIFFIO_RX_B44N)
OV10640_DATA_HS_N3: J2.18 R76.1 R78.1 U1.AB17(DIFFIO_RX_B58N)
OV10640_DATA_HS_N4: J2.21 R84.1 R85.1 U1.AB16(DIFFIO_RX_B42N)
OV10640_DATA_HS_P1: J2.8 R79.1 R81.2 U1.AA20(DIFFIO_RX_B50P)
OV10640_DATA_HS_P2: J2.14 R87.1 R88.2 U1.AB20(DIFFIO_RX_B44P)
OV10640_DATA_HS_P3: J2.17 R72.1 R74.2 U1.AB18(DIFFIO_RX_B58P)
OV10640_DATA_HS_P4: J2.20 R80.1 R82.2 U1.AA16(DIFFIO_RX_B42P)
OV10640_DATA_LP_N1: R86.2 TP48.1(TP) U1.N22(DIFFIO_RX_R31N)
OV10640_DATA_LP_N2: R93.2 TP54.1(TP) U1.V22(DIFFIO_RX_R24N)
OV10640_DATA_LP_N3: R78.2 TP60.1(TP) U1.W22(DIFFIO_RX_R20N)
OV10640_DATA_LP_N4: R85.2 TP66.1(TP) U1.AA22(DIFFIO_RX_R2N)
OV10640_DATA_LP_P1: R79.2 TP45.1(TP) U1.P21(DIFFIO_RX_R31P)
OV10640_DATA_LP_P2: R87.2 TP50.1(TP) U1.V21(DIFFIO_RX_R24P)
OV10640_DATA_LP_P3: R72.2 TP57.1(TP) U1.Y22(DIFFIO_RX_R20P)
OV10640_DATA_LP_P4: R80.2 TP63.1(TP) U1.AA21(DIFFIO_RX_R2P)
OV10640_FSIN: J2.32 U1.P8(DIFFIO_RX_L47N)
OV10640_G_RDY: J2.28 U1.R4(DIFFIO_RX_L39N)
OV10640_GYRO_INT: J2.27 U1.N9(DIFFIO_RX_L41P)
OV10640_XM_INT1: J2.31 U1.R7(DIFFIO_RX_L47P)
OV10640_XM_INT2: J2.30 U1.R5(DIFFIO_RX_L39P)
PMODA_D0: U1.A6(DIFFIO_RX_T41N) ; also on sheet 17
PMODA_D1: U1.E8(DIFFIO_RX_T48P) ; also on sheet 17
PMODA_D2: U1.B4(DIFFIO_RX_T46N) ; also on sheet 17
PMODA_D3: U1.A5(DIFFIO_RX_T43P) ; also on sheet 17
PMODA_D4: U1.B7(DIFFIO_RX_T41P) ; also on sheet 17
PMODA_D5: U1.E9(DIFFIO_RX_T44N) ; also on sheet 17
PMODA_D6: U1.A4(DIFFIO_RX_T43N) ; also on sheet 17
PMODA_D7: U1.B5(DIFFIO_RX_T47P) ; also on sheet 17
PMODB_D0: U1.C8(DIFFIO_RX_T39P) ; also on sheet 17
PMODB_D1: U1.D8(DIFFIO_RX_T42P) ; also on sheet 17
PMODB_D2: U1.A3(DIFFIO_RX_T45N) ; also on sheet 17
PMODB_D3: U1.A2(DIFFIO_RX_T45P) ; also on sheet 17
PMODB_D4: U1.B3(DIFFIO_RX_T46P) ; also on sheet 17
PMODB_D5: U1.C2(DIFFIO_RX_T53N) ; also on sheet 17
PMODB_D6: U1.B1(DIFFIO_RX_T51N) ; also on sheet 17
PMODB_D7: U1.B2(DIFFIO_RX_T51P) ; also on sheet 17
USB_ADDR0: U1.E1(DIFFIO_RX_L21N) ; also on sheet 16
USB_ADDR1: U1.G3(DIFFIO_RX_L6P/ADC2IN6) ; also on sheet 16
USB_CLK: U1.E11(DIFFIO_RX_T38P/CLK4P) ; also on sheet 15
USB_DATA0: U1.H4(DIFFIO_RX_L6N/ADC2IN5) ; also on sheet 16
USB_DATA1: U1.F1(DIFFIO_RX_L23P) ; also on sheet 16
USB_DATA2: U1.E4(DIFFIO_RX_L2N/ADC2IN1) ; also on sheet 16
USB_DATA3: U1.E3(DIFFIO_RX_L2P/ADC2IN8) ; also on sheet 16
USB_DATA4: U1.G1(DIFFIO_RX_L23N) ; also on sheet 16
USB_DATA5: U1.H1(DIFFIO_RX_L22N) ; also on sheet 16
USB_DATA6: U1.H3(DIFFIO_RX_L5P/ADC1IN6) ; also on sheet 16
USB_DATA7: U1.J3(DIFFIO_RX_L8P/ADC2IN2) ; also on sheet 16
USB_EMPTY: U1.F3(DIFFIO_RX_L4P/ADC2IN4) ; also on sheet 16
USB_FULL: U1.F4(DIFFIO_RX_L1P/ADC1IN2) ; also on sheet 16
USB_OEn: U1.F2(DIFFIO_RX_L21P) ; also on sheet 16
USB_RDn: U1.J4(DIFFIO_RX_L5N/ADC1IN5) ; also on sheet 16
USB_RESETn: U1.K2(DIFFIO_RX_L19N) ; also on sheet 15
USB_SCL: U1.D2(DIFFIO_RX_L16P) ; also on sheet 16
USB_SDA: U1.D3(DIFFIO_RX_L16N) ; also on sheet 16
USB_WRn: U1.J1(DIFFIO_RX_L22P) ; also on sheet 15
USER_CLKIN_N_MAX10: U1.K21(DIFFIO_RX_R40N/CLK3N) ; also on sheet 17
USER_CLKIN_P: R271.1 ; also on sheet 17
USER_CLKIN_P_MAX10: R270.2 R271.2 U1.K22(DIFFIO_RX_R40P/CLK3P)
USER_DIPSW0: U1.R18(DIFFIO_RX_R32P/DQS1R) ; also on sheet 18
USER_DIPSW1: U1.T19(DIFFIO_RX_R27P/DQ1R) ; also on sheet 18
USER_DIPSW2: U1.T18(DIFFIO_RX_R27N/DM1R) ; also on sheet 18
USER_DIPSW3: U1.U19(DIFFIO_RX_R19N) ; also on sheet 18
USER_DIPSW4: U1.G4(DIFFIO_RX_L4N/ADC2IN3) ; also on sheet 18
USER_DIPSW5: U1.F5(DIFFIO_RX_L1N/ADC1IN1) ; also on sheet 18
USER_IO0: U1.A17(DIFFIO_RX_T10N) ; also on sheet 17
USER_IO1: U1.B19(DIFFIO_RX_T6N) ; also on sheet 17
USER_IO2: U1.E16(DIFFIO_RX_T1P) ; also on sheet 17
USER_IO3: U1.C19(DIFFIO_RX_T6P) ; also on sheet 17
USER_IO4: U1.F16(DIFFIO_RX_T5P) ; also on sheet 17
USER_IO5: U1.A19(DIFFIO_RX_T8N) ; also on sheet 17
USER_IO6: U1.A20(DIFFIO_RX_T8P) ; also on sheet 17
USER_IO7: U1.C18(DIFFIO_RX_T7P) ; also on sheet 17
USER_IO8: U1.C17(DIFFIO_RX_T2N) ; also on sheet 17
USER_IO9: U1.D17(DIFFIO_RX_T2P) ; also on sheet 17
USER_LED0: U1.C3(DIFFIO_RX_T53P) ; also on sheet 18
USER_LED1: U1.C4(DIFFIO_RX_T47N) ; also on sheet 18
USER_LED2: U1.C5(DIFFIO_RX_T49P) ; also on sheet 18
USER_LED3: U1.D5(DIFFIO_RX_T49N) ; also on sheet 18
USER_LED4: U1.C7(DIFFIO_RX_T39N) ; also on sheet 18
USER_LVDS_N0: U1.Y10(DIFFIO_TX_RX_B22N) ; also on sheet 17
USER_LVDS_N1: U1.W7(DIFFIO_TX_RX_B13N) ; also on sheet 17
USER_LVDS_N2: U1.AA17(DIFFIO_TX_RX_B43N) ; also on sheet 17
USER_LVDS_N3: U1.Y13(DIFFIO_TX_RX_B37N) ; also on sheet 17
USER_LVDS_N4: U1.W9(DIFFIO_TX_RX_B11N) ; also on sheet 17
USER_LVDS_N5: U1.V7(DIFFIO_TX_RX_B7N) ; also on sheet 17
USER_LVDS_N6: U1.W5(DIFFIO_TX_RX_B1N) ; also on sheet 17
USER_LVDS_N7: U1.W4(DIFFIO_TX_RX_B5N) ; also on sheet 17
USER_LVDS_N8: U1.AA6(DIFFIO_TX_RX_B16N) ; also on sheet 17
USER_LVDS_P0: U1.AA10(DIFFIO_TX_RX_B22P) ; also on sheet 17
USER_LVDS_P1: U1.W8(DIFFIO_TX_RX_B13P) ; also on sheet 17
USER_LVDS_P2: U1.Y17(DIFFIO_TX_RX_B43P) ; also on sheet 17
USER_LVDS_P3: U1.Y14(DIFFIO_TX_RX_B37P) ; also on sheet 17
USER_LVDS_P4: U1.W10(DIFFIO_TX_RX_B11P) ; also on sheet 17
USER_LVDS_P5: U1.V8(DIFFIO_TX_RX_B7P) ; also on sheet 17
USER_LVDS_P6: U1.W6(DIFFIO_TX_RX_B1P) ; also on sheet 17
USER_LVDS_P7: U1.W3(DIFFIO_TX_RX_B5P) ; also on sheet 17
USER_LVDS_P8: U1.AA7(DIFFIO_TX_RX_B16P) ; also on sheet 17
USER_PB0: U1.R20(DIFFIO_RX_R28N/DQ1R) ; also on sheet 18
USER_PB1: U1.Y20(DIFFIO_RX_R22P) ; also on sheet 18
USER_PB2: U1.Y21(DIFFIO_RX_R22N) ; also on sheet 18
USER_PB3: U1.U20(DIFFIO_RX_R23N) ; also on sheet 18
VREF_1V2HSTL: C4.2 C8.1 R9.1 R11.2 U1.P22(VREFB5N0)
VREF_1V8HSTL: C1.1 C3.1 R1.1 R2.2 U1.M2(VREFB2N0)
VREF_LPDDR2: C6.2 C9.1 R10.1 R12.2 U1.D21(VREFB6N0)
N17604176: C31.1 R73.1 R75.2
N17604218: C33.1 R81.1 R83.2
N17604268: C35.1 R88.1 R90.2
N17605267: C32.1 R74.1 R76.2
N17605327: C34.1 R82.1 R84.2

Not connected (* = marked no-connect by the designer): J1 1* 2*; J2 35* 36*; U1 A15(TBD7)* AA1(DIFFIO_RX_B6N) AA2(DIFFIO_RX_B6P) AA3(VREFB3N0) AA8(DIFFIO_RX_B21N) AA9(DIFFIO_RX_B23N) AA11(DIFFIO_TX_RX_B28N)* AA12(DIFFIO_TX_RX_B28P)* AA13(VREFB4N0) AA14(DIFFIO_RX_B38N) AA15(DIFFIO_RX_B40N) AA19(DIFFIO_RX_B46N) AB4(TBD3) AB8(DIFFIO_RX_B21P) AB9(DIFFIO_RX_B23P) AB14(TBD4) AB15(DIFFIO_RX_B38P) B15(VREFB7N0)* C1(VREFB1N0)* C6(TBD8)* D1(TBD1)* D7(VREFB8N0)* D10(DIFFIO_RX_T44P/DEV_OE) F7(DIFFIO_RX_T48N/CRC_ERROR) K8(DIFFIO_RX_L15N)* L8(DIFFIO_RX_L20N)* L9(DIFFIO_RX_L20P)* M1(TBD2) P9(DIFFIO_TX_RX_B9P) P10(DIFFIO_TX_RX_B15P)* P12(DIFFIO_TX_RX_B26P)* P13(DIFFIO_TX_RX_B36P)* R9(DIFFIO_TX_RX_B9N) R10(DIFFIO_TX_RX_B15N)* R12(DIFFIO_TX_RX_B26N)* R13(DIFFIO_TX_RX_B36N)* U6(DIFFIO_TX_RX_B3N)* U7(DIFFIO_TX_RX_B3P)* U15(DIFFIO_TX_RX_B41N)* V11(DIFFIO_TX_RX_B24N) V12(DIFFIO_TX_RX_B24P) V13(DIFFIO_TX_RX_B34N)* V14(DIFFIO_TX_RX_B39N)* V15(DIFFIO_TX_RX_B45N)* V16(DIFFIO_TX_RX_B41P)* W11(DIFFIO_RX_B25N)* W12(DIFFIO_RX_B35N) W13(DIFFIO_RX_B35P) W14(DIFFIO_TX_RX_B34P)* W15(DIFFIO_TX_RX_B39P)* W16(DIFFIO_TX_RX_B45P)* W18(DIFFIO_TX_RX_B49P) Y3(DIFFIO_RX_B14N)* Y4(DIFFIO_RX_B14P)* Y5(DIFFIO_RX_B8N) Y6(DIFFIO_RX_B8P) Y7(DIFFIO_RX_B10N)* Y8(DIFFIO_RX_B10P)* Y11(DIFFIO_RX_B25P)* Y16(DIFFIO_RX_B40P) Y18(DIFFIO_RX_B46P) Y19(DIFFIO_TX_RX_B49N); U2 A1(DNU0)* A2(DNU1)* A9(DNU2)* A10(DNU3)* B1(DNU4)* B2(NC0)* B3(NC1)* B7(NC2)* B8(NC3)* B9(NC4)* B10(DNU5)* C3(RFU0)* C8(NC5)* D6(NC6)* D7(NC7)* D8(NC8)* D9(NC9)* E5(NC10)* E6(NC11)* E7(NC12)* J2(NC13)* K2(RFU1)* K3(RFU2)* L2(RFU3)* L3(RFU4)* N5(NC14)* N6(NC15)* N7(NC16)* P6(NC17)* P7(NC18)* P8(NC19)* P9(NC20)* R3(NC21)* R8(NC22)* T1(DNU6)* T2(NC23)* T3(NC24)* T7(NC25)* T8(NC26)* T9(NC27)* T10(DNU7)* U1(DNU8)* U2(DNU9)* U9(DNU10)* U10(DNU11)*

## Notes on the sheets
sheet 1
- NOTES:
- REV
- DATE
- PAGES
- DESCRIPTION
- 1.
- Project Drawing Numbers:
       Raw PCB
       Gerber Files
       PCB Design Files
       Assembly Drawing
       Fab Drawing
       Schematic Drawing
       PCB Film
       Bill of Materials
       Schematic Design Files
       Functional Specification
       PCB Layout Guidelines
       Assembly Rework
- 100-0321404-A1.1
  110-0321404-A1.1
  120-0321404-A1.1
  130-0321404-A1.1
  140-0321404-A1.1
  150-0321404-A1.1
  160-0321404-A1.1
  170-0321404-A1.1
  180-0321404-A1.2
  210-0321404-A1.1
  220-0321404-A1.1
  320-0321404-A1.1
- A1
- A1.1
- Jun 19 2015
- All
- 1
- Initial Revision A Release.
- Update block diagram.
- Sep 15 2015
- 2
- Update power tree.
- 10
- Delete C12.
- 18
- Add note for SW2.4 MAX10_BYPASSn.
- 22
- Change the value of C219 from DNI to 47uF.
- 23
- Add R315 to 1.2V_VCCIO.
- A1.2
- Dec 23 2015
- 25
- 10
- Change LPDDR2_IS43LD16640A-3BL(333MHz part) to IS43LD16640A-25BL (400MHz part)
  due to Altera IP recommendation.
- Change the value of C232 from 100uF to DNI.
- MAX 10 FPGA 10M50 Evaluation Kit Board
- PAGE
- DESCRIPTION
- 1
- Title, Notes, Block Diagram, Rev. History
- 2
- Power Tree
- 3
- Clock Tree
- 4
- MAX10 Banks 1 & 2
- 5
- MAX10 Banks 3 & 4
- 6
- MAX10 Banks 5 & 6
- 7
- MAX10 Banks 7 & 8
- 8
- MAX10 Clocks
- 9
- MAX10 Configuration
- 10
- LPDDR2 SDRAM
- 11
- MIPI CSI-2 Tx D-PHY LI-USB3
- 12
- MIPI CSI-2 Rx D-PHY OV10640
- 13
- MIPI CSI-2 Rx D-PHY OV5640
- 14
- HDMI (VIDEO ONLY)
- 15
- On-Board USB Blaster II -1
- 16
- On-Board USB Blaster II -2
- 17
- PMOD, GPIO, LVDS UserIO
- 18
- Pushbutton, Switch, LED
- 19
- Clocking
- 20
- QSPI Flash
- 21
- Hot Swap and Power 3.3 V
- 22
- Power 2.5 V & 1.8V
- 23
- Power 1.2V
- 24
- MAX 10 Power & Ground
- 25
- Decoupling
- Altera Corporation, 301, Bibo Rd #888, Shanghai, China, 201203
- Copyright (c) 2015, Altera Corporation. All Rights Reserved.
sheet 2
- POWER TREE
- Altera Corporation, 301, Bibo Rd #888, Shanghai, China, 201203
- Copyright (c) 2015, Altera Corporation. All Rights Reserved.
sheet 3
- CLOCK TREE
- Altera Corporation, 301, Bibo Rd #888, Shanghai, China, 201203
- Copyright (c) 2015, Altera Corporation. All Rights Reserved.
sheet 4
- MAX10 BANKS 1 & 2
- MAX10 USB Interface
- ( VCCIO = 3.3V )
- ( VCCIO = 1.8V )
- OV5640 CSI-2 RX Interface
- OV10640 CSI-2 RX Interface
- ( VCCIO = 3.3V )
- LI-USB3 CSI-2 TX Interface
- Misc
- User DIP Switch
- Altera Corporation, 301, Bibo Rd #888, Shanghai, China, 201203
- Copyright (c) 2015, Altera Corporation. All Rights Reserved.
sheet 5
- MAX10 BANKS 3 & 4
- User LVDS IO
- ( VCCIO = 2.5V )
- ( VCCIO = 2.5V )
- OV10640 Interface
- OV5640 Interface
- LI-USB3 CSI-2 TX Interface
- Altera Corporation, 301, Bibo Rd #888, Shanghai, China, 201203
- Copyright (c) 2015, Altera Corporation. All Rights Reserved.
sheet 6
- MAX10 BANKS 5 & 6
- LPDDR2 Interface
- ( VCCIO = 1.2V )
- ( VCCIO = 1.2V )
- F21 and F20 are restricted pins
  while implementating LPDDR2.
- OV10640 Interface
- U22 and U21 are restricted pins
  while implementating LPDDR2.
- F18 and E19 are restricted pins
  while implementating LPDDR2.
- OV5640 Interface
- L22 and M21 are restricted pins
  while implementating LPDDR2.
- E17 and F17 are restricted pins
  while implementating LPDDR2.
- User DIP Switch
- User Pushbuttons
- Reference Voltages of 1.2V HSTL and LPDDR2
- Altera Corporation, 301, Bibo Rd #888, Shanghai, China, 201203
- Copyright (c) 2015, Altera Corporation. All Rights Reserved.
sheet 7
- MAX10 BANKS 7 & 8
- User IO
- ( VCCIO = 3.3V )
- ( VCCIO = 3.3V )
- PMOD
- HDMI TX
- Flash
- LI-USB3 CSI-2 TX Interface
- User LED
- Altera Corporation, 301, Bibo Rd #888, Shanghai, China, 201203
- Copyright (c) 2015, Altera Corporation. All Rights Reserved.
sheet 8
- MAX10 CLOCKS
- LPDDR2 Interface
- ( VCCIO = 1.8V )
- OV5640 Interface
- ( VCCIO = 2.5V )
- OV10640 Interface
- ( VCCIO = 2.5V )
- ( VCCIO = 1.2V )
- Si5338
- ( VCCIO = 3.3V )
- USB Blaster II
- User LVDS
- Note: CLK125M_LVDS is the clock
  source provided to external LVDS user interface.
  USER_CLKIN_P is used for external sigle-ended
  clock input.
  USER_CLKIN_P/N is used for external differential
  clock input.
- HDMI
- Altera Corporation, 301, Bibo Rd #888, Shanghai, China, 201203
- Copyright (c) 2015, Altera Corporation. All Rights Reserved.
sheet 9
- MAX10 CONFIGURATION
- Configuration
- ( VCCIO = 3.3V )
- ( VCCIO = 3.3V )
- Altera Corporation, 301, Bibo Rd #888, Shanghai, China, 201203
- Copyright (c) 2015, Altera Corporation. All Rights Reserved.
sheet 10
- LPDDR2 SDRAM x 16
- LPDDR2 Interface
- CAD Note:
  Place resistors near LPDDR2
  VREFCA and VREFDQ pins
- LPDDR2 Power Decoupling
- CAD Note:
  Place decoupling caps near LPDDR2.
- CAD Note:
  Place decoupling caps near LPDDR2.
- Altera Corporation, 301, Bibo Rd #888, Shanghai, China, 201203
- Copyright (c) 2015, Altera Corporation. All Rights Reserved.
sheet 11
- MIPI CSI-2 TX D-PHY
- CAD Note:
  Place resistors near FPGA side.
- CAD Note:
  Place resistors near FPGA side.
- LI-USB3 CSI-2 TX Interface
- CAD Note:
  Place resistors near FPGA side.
- CAD Note:
  Place resistors near FPGA side.
- CAD Note:
  Place resistors near FPGA side.
- CAD Note:
  Place C29 and C30 near J1 connector.
- Pull-up Options for MIPI TX
- Altera Corporation, 301, Bibo Rd #888, Shanghai, China, 201203
- Copyright (c) 2015, Altera Corporation. All Rights Reserved.
sheet 12
- MIPI CSI-2 RX D-PHY OV10640
- CAD Note:
  Place resistors near FPGA side.
- CAD Note:
  Place resistors near FPGA side.
- OV10640 CSI-2 RX Interface
- CAD Note:
  Place resistors near FPGA side.
- CAD Note:
  Place resistors near FPGA side.
- CAD Note:
  Place resistors near FPGA side.
- CAD Note:
  Place capacitors near J2 connector.
- Altera Corporation, 301, Bibo Rd #888, Shanghai, China, 201203
- Copyright (c) 2015, Altera Corporation. All Rights Reserved.
